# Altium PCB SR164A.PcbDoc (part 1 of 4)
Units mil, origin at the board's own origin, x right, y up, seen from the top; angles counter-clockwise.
Board outline 6100 x 4100 mil, 6 copper layers (Top Layer, Signal Layer 1, Signal Layer 2, Signal Layer 3, Signal Layer 4, Bottom Layer), stack 61.4 mil thick; 254 components, 116 nets, 656 pads, 2538 vias.
Unrouted connection lines stored in the file: 13.
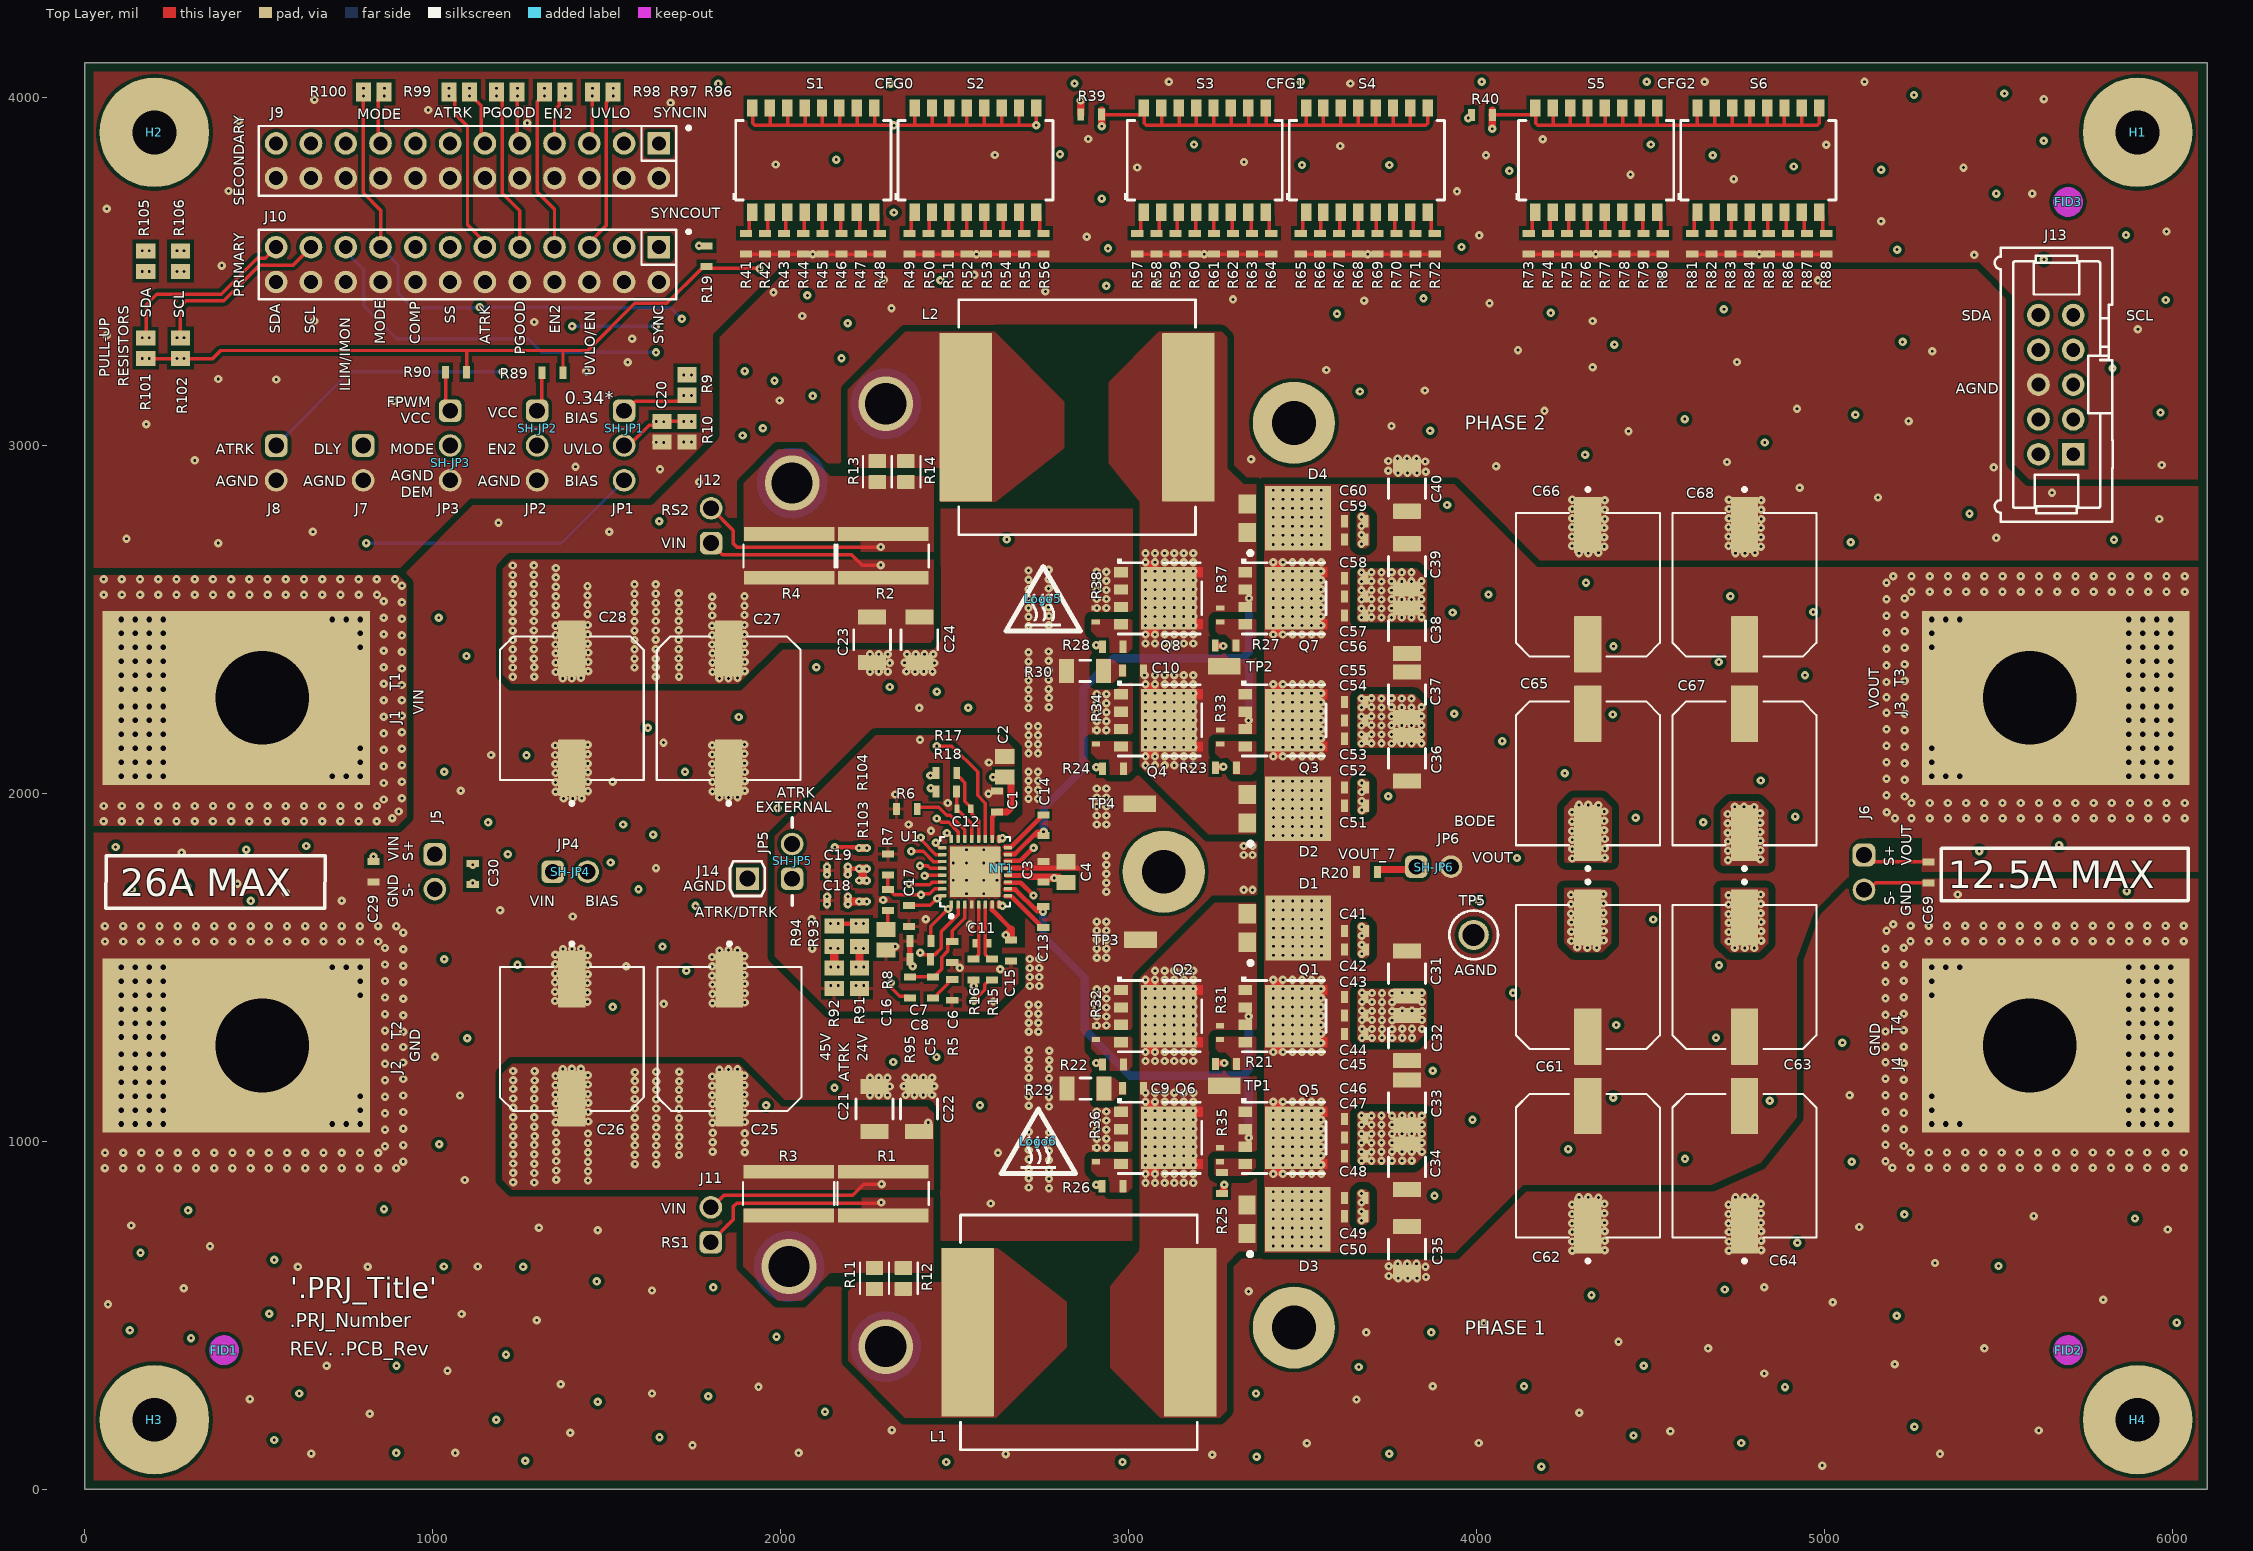
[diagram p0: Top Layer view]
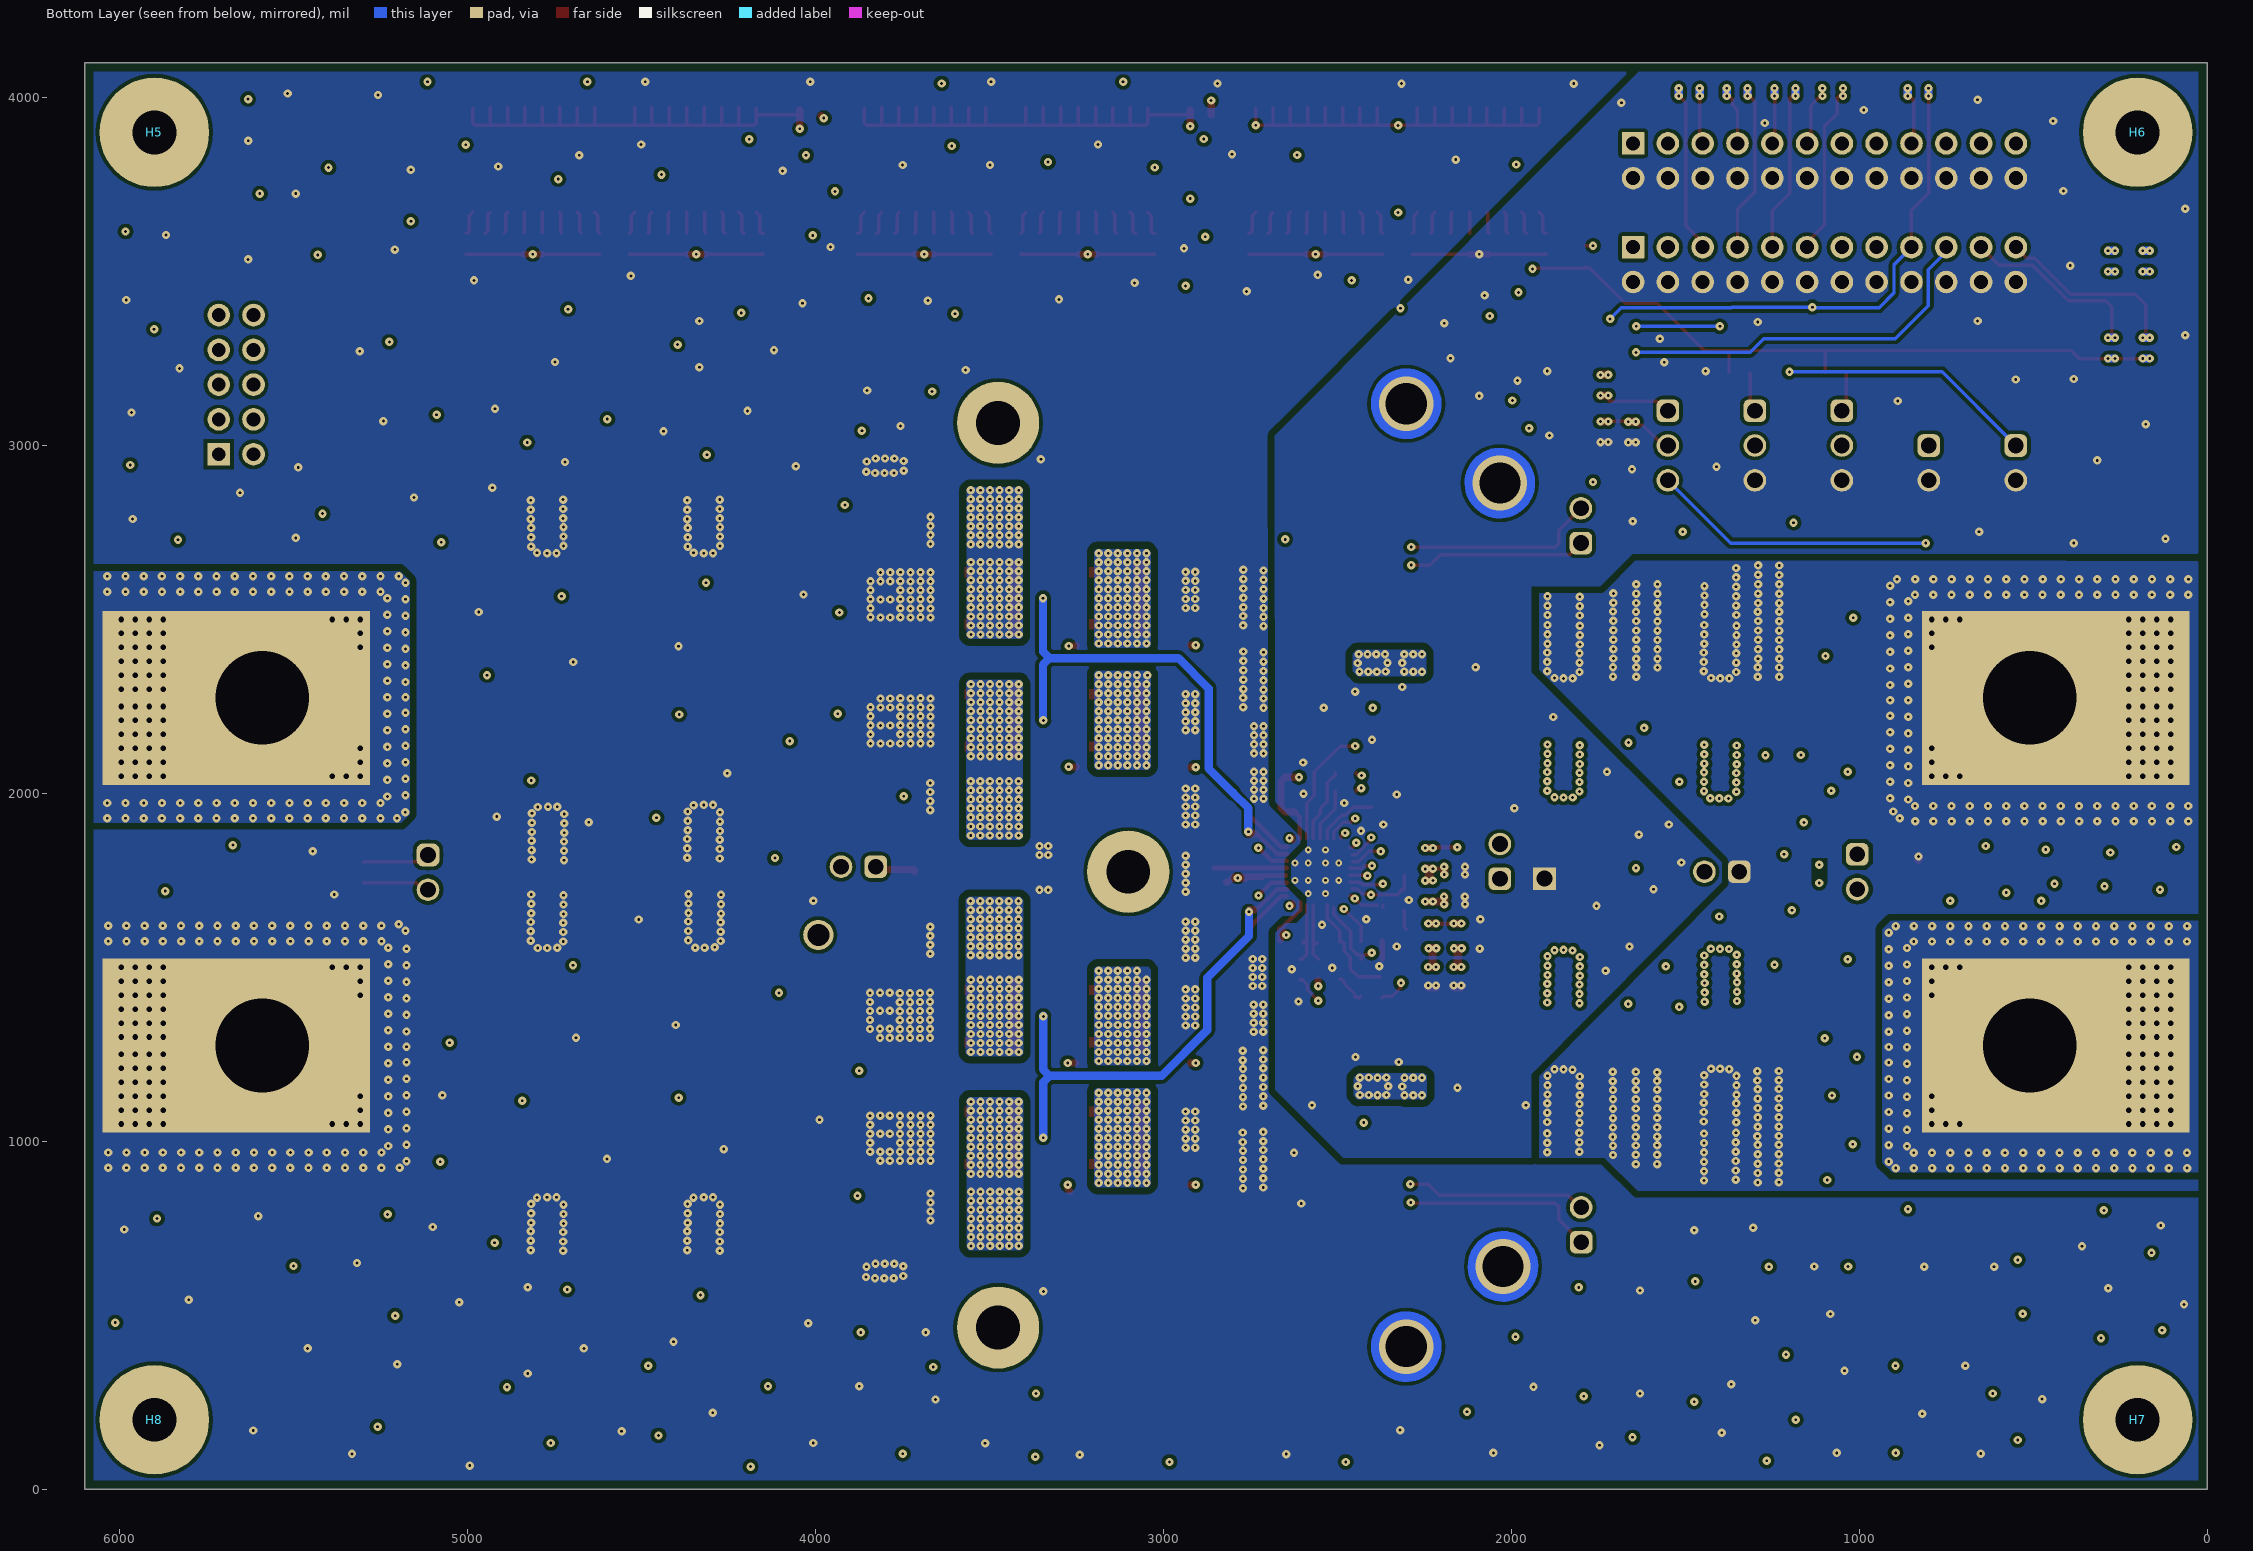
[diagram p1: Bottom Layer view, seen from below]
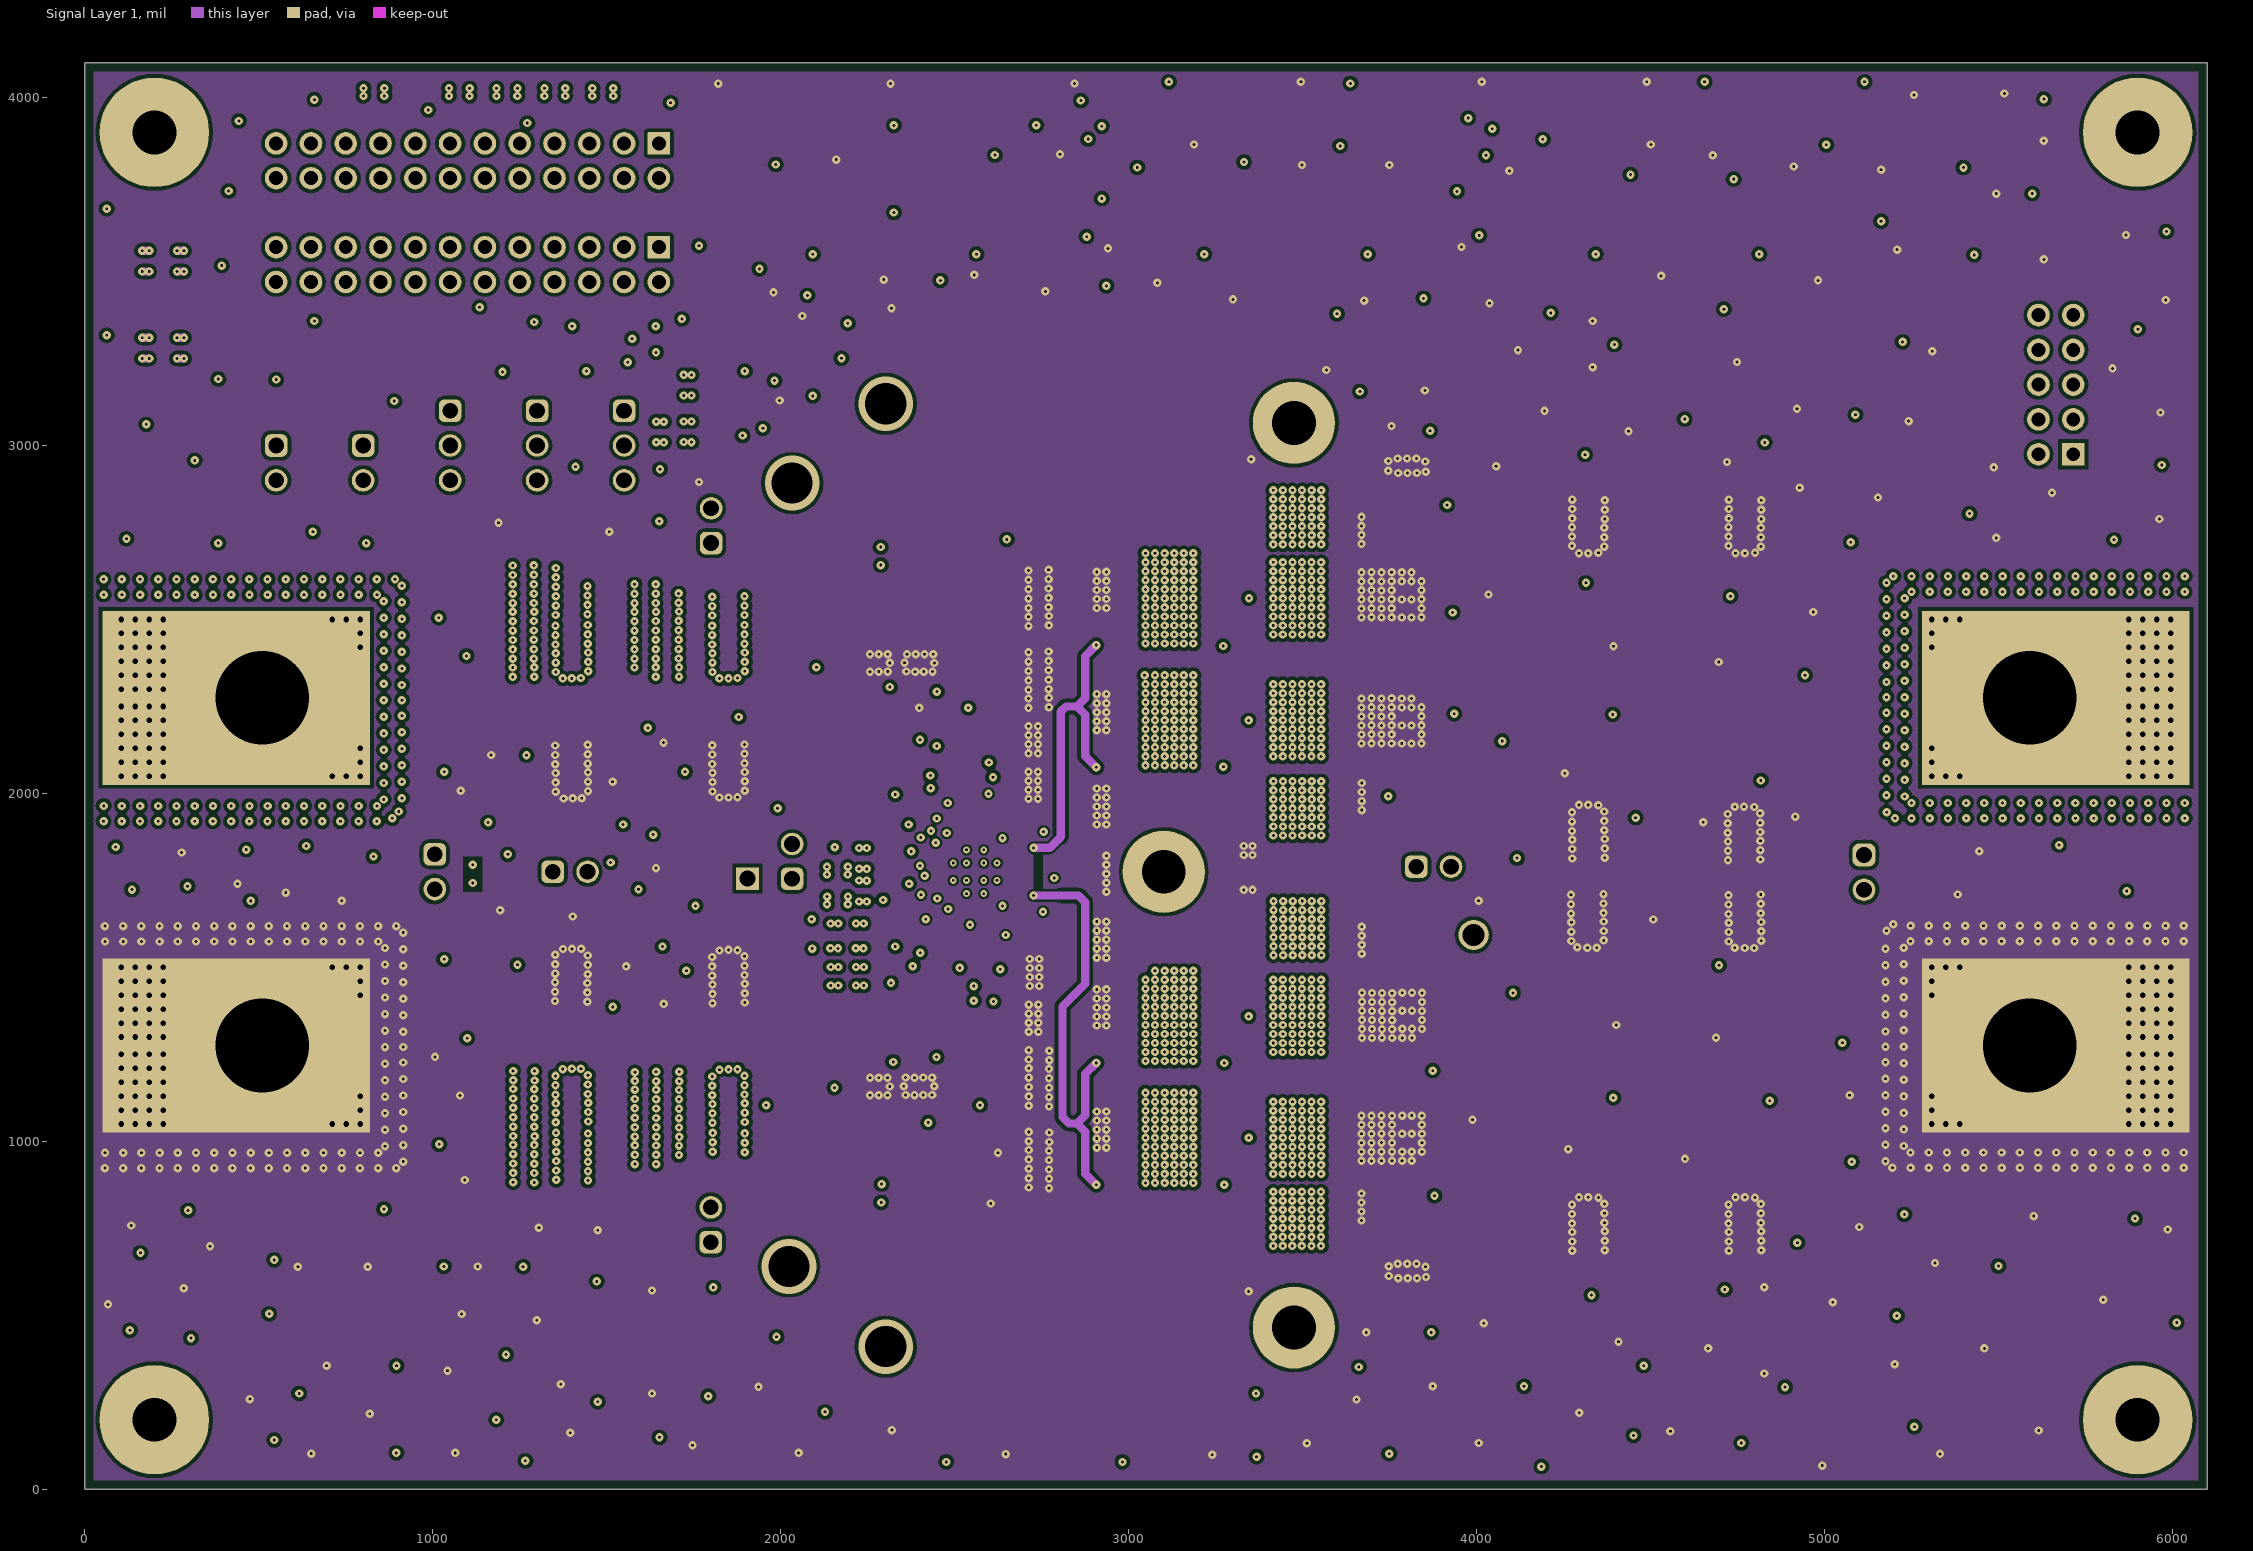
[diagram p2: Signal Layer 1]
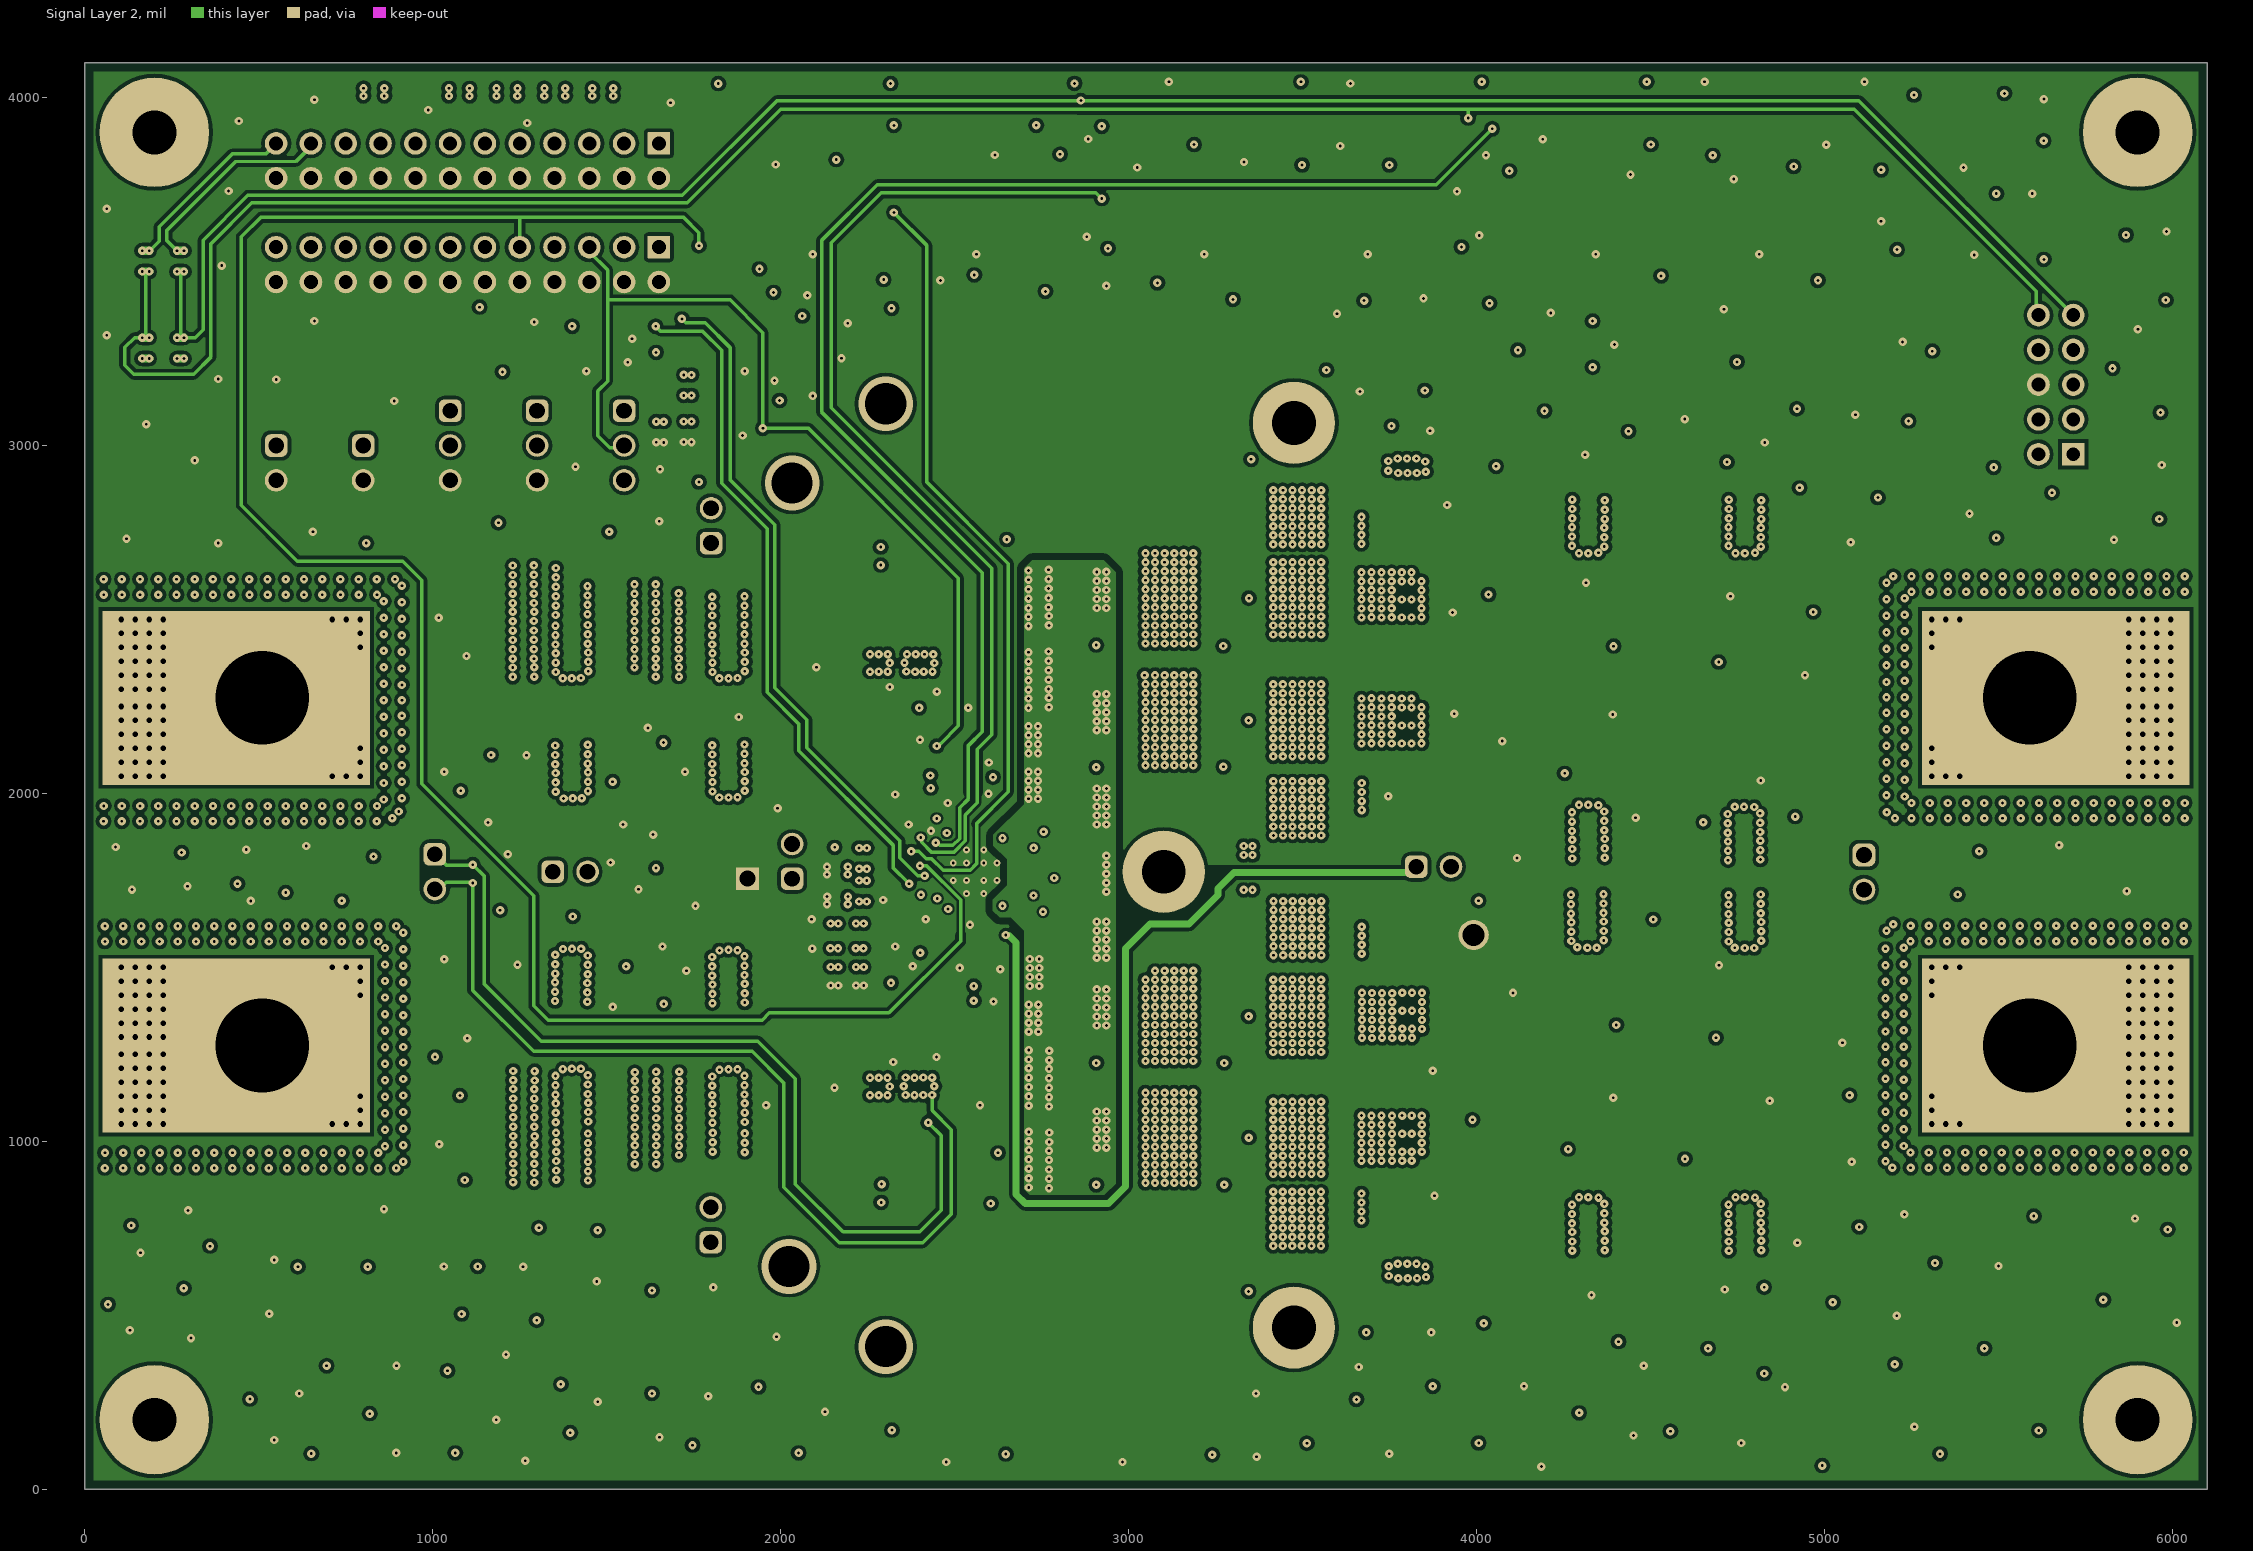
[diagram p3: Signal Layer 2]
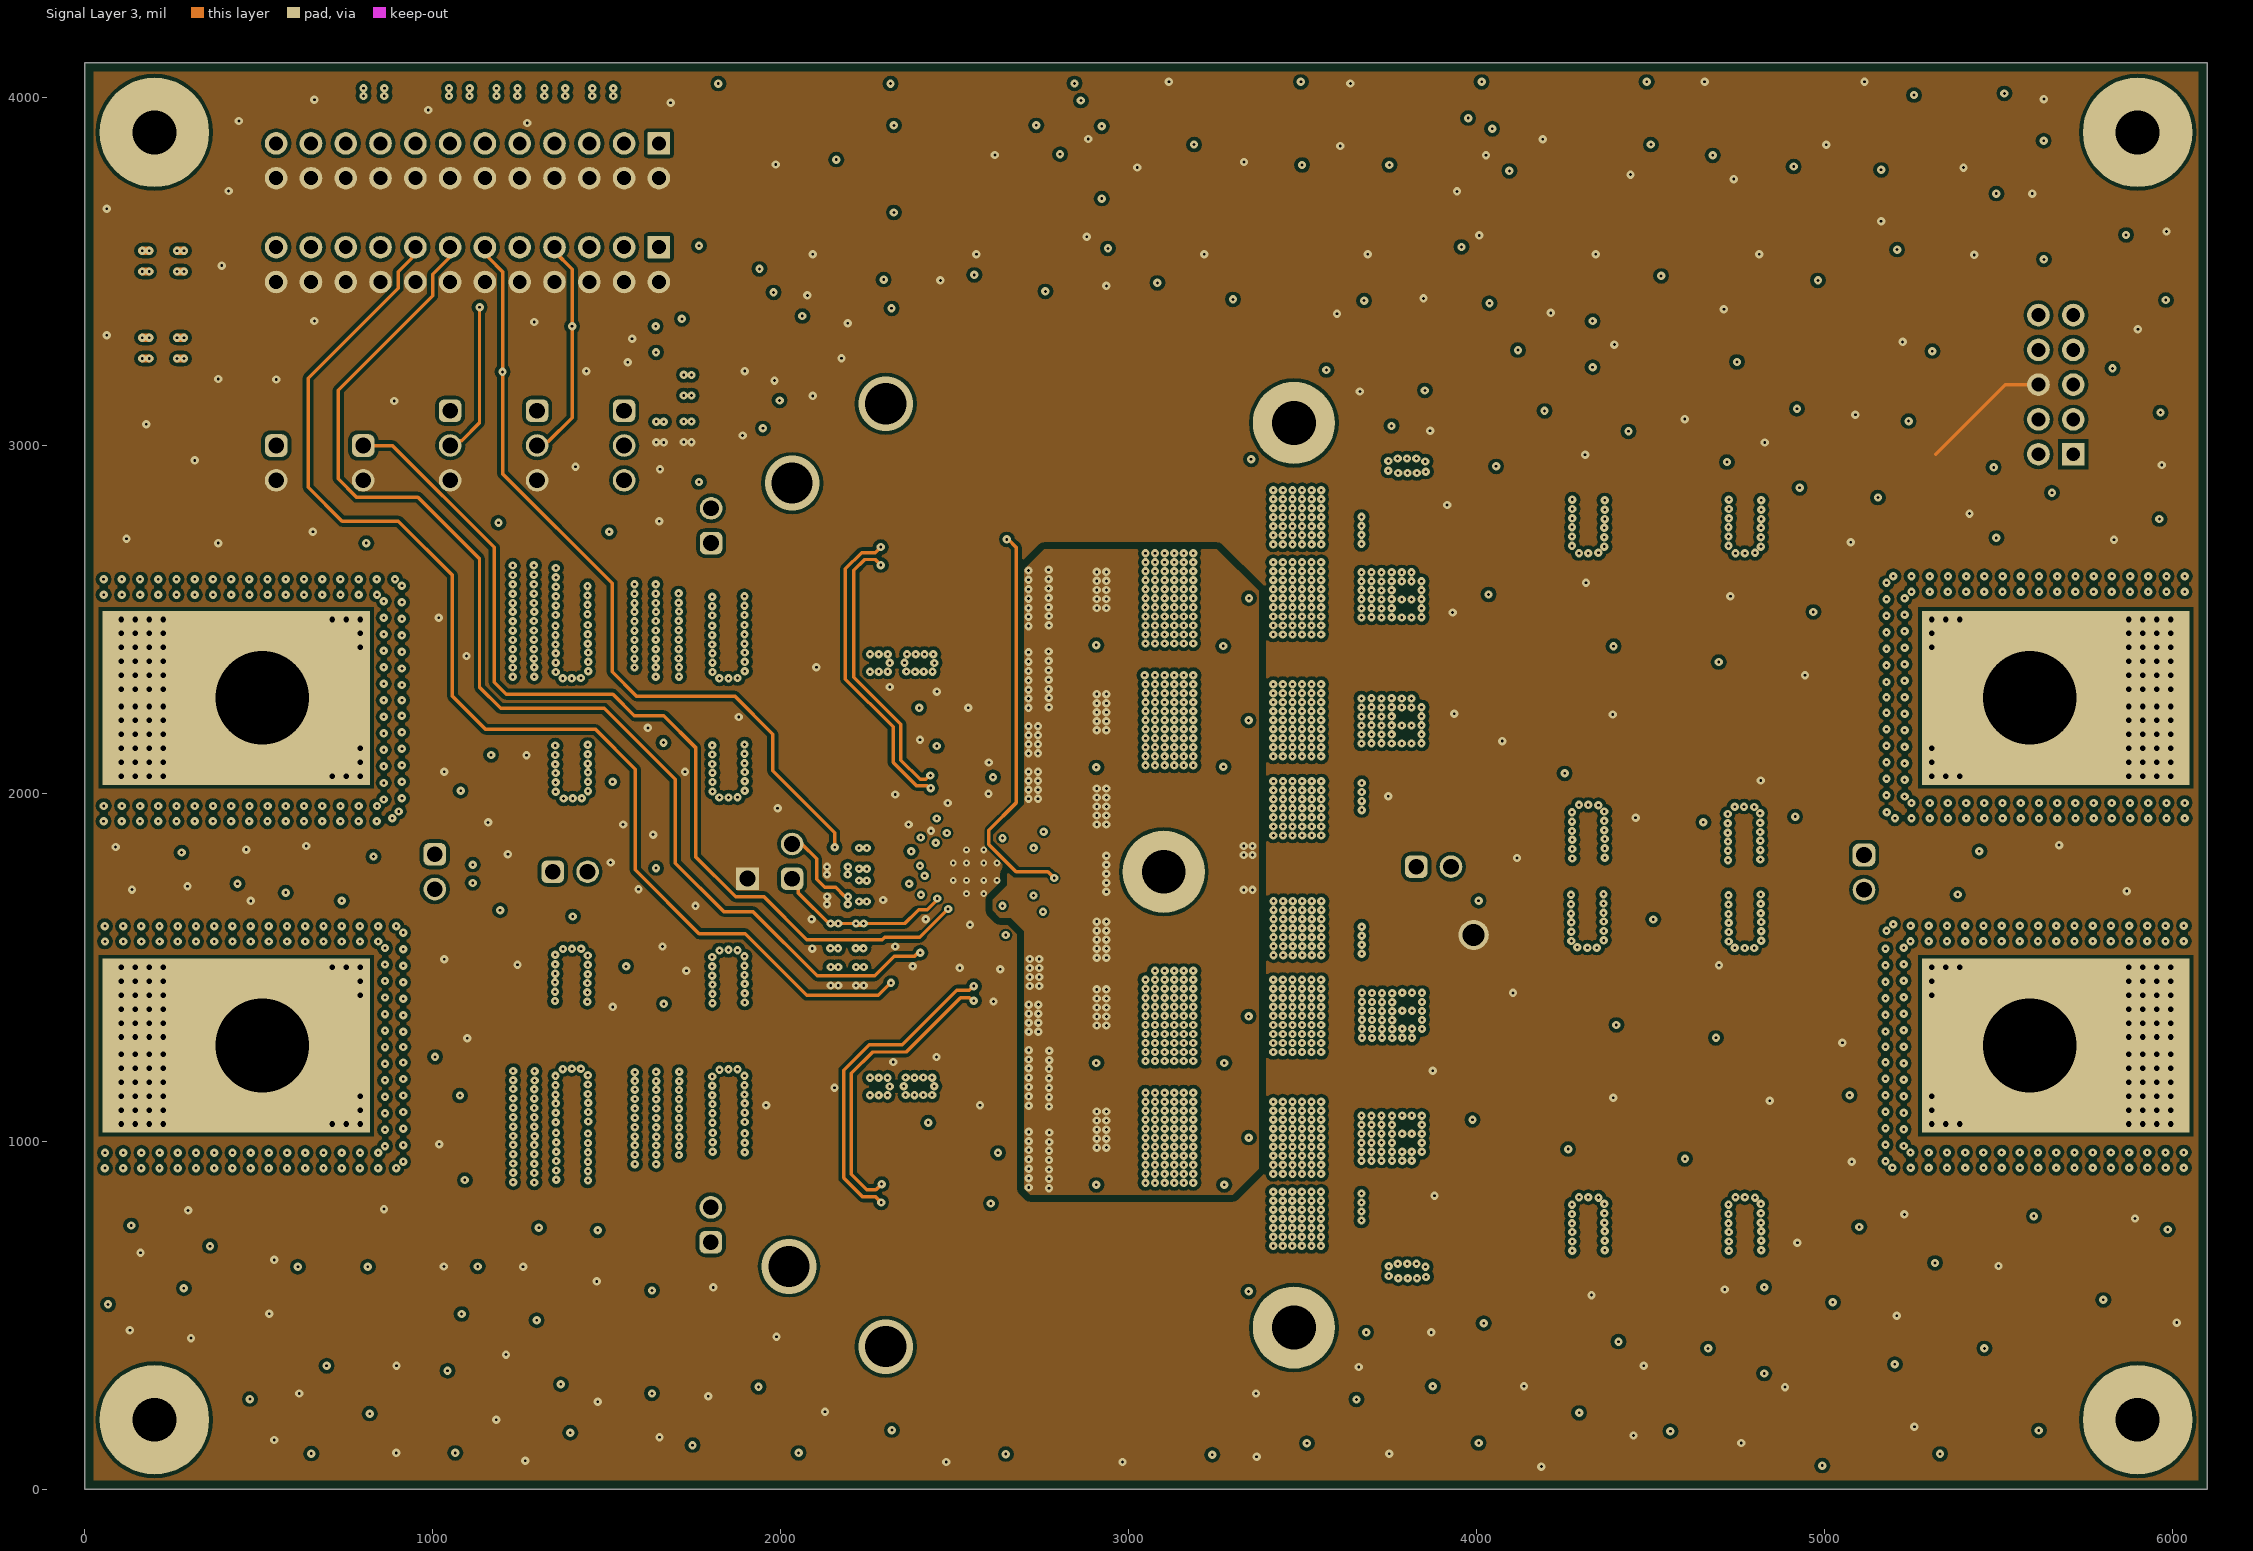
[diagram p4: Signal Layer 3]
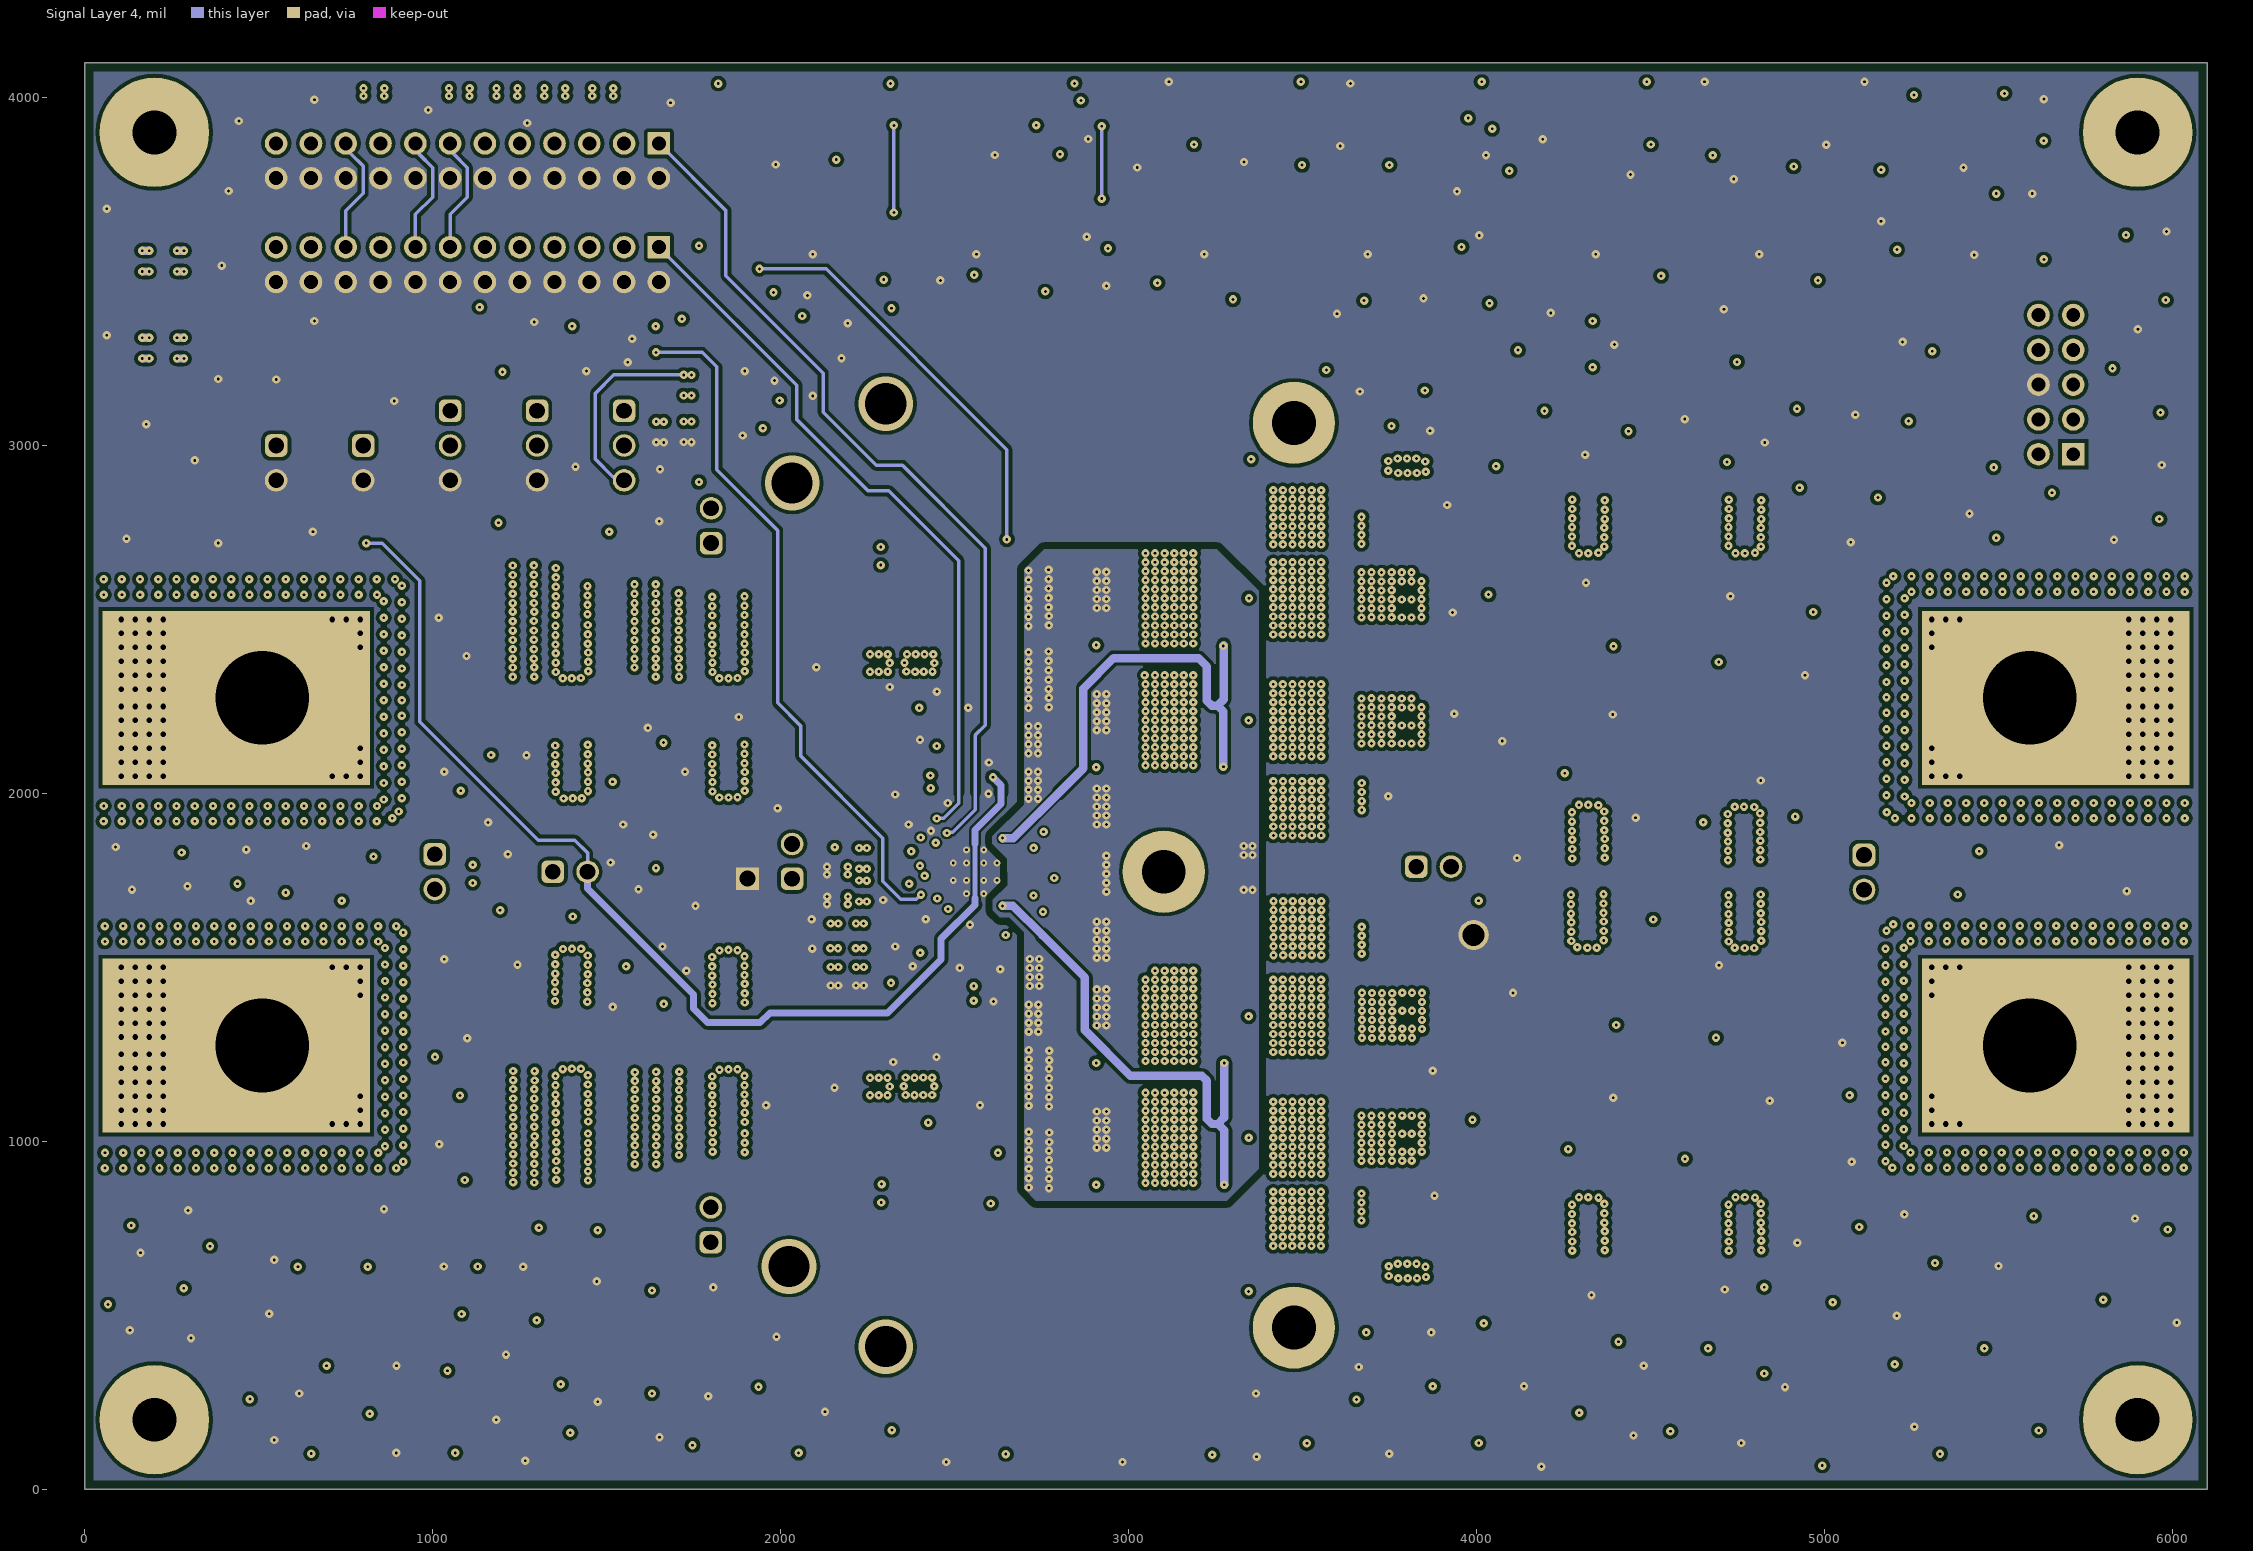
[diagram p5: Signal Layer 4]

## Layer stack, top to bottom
Top Solder: solder mask 0.5, Solder Resist, Dk 3.5
Top Layer: signal copper 2.8
Dielectric 1: prepreg 7, FR-4 High Tg, Dk 4.2
Signal Layer 1: signal copper 1.4
Dielectric 2: core 14, FR-4 High Tg, Dk 4.2
Signal Layer 2: signal copper 1.4
Dielectric 4: prepreg 8.2, FR-4 High Tg, Dk 4.2
Signal Layer 3: signal copper 1.4
Dielectric 5: core 14, FR-4 High Tg, Dk 4.2
Signal Layer 4: signal copper 1.4
Dielectric 3: prepreg 7, FR-4 High Tg, Dk 4.2
Bottom Layer: signal copper 2.8
Bottom Solder: solder mask 0.5, Solder Resist, Dk 3.5

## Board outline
0,0 6100,0 6100,4100 0,4100

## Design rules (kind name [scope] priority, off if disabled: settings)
AcuteAngle [All] p1: minimum=4.50000000000000E+0001 checktracksonly=FALSE
AssemblyTestPointUsage [All] p1: valid=2
BoardOutlineClearance BoardOutlineClearance_MountingHoles [OnCopper and InComponentClass('Mounting Holes')] p1: gap=39.37 ignorepadtopadclearanceinfootprint=FALSE
BoardOutlineClearance BoardOutlineClearance_Poly [OnCopper and IsPoly] p2: gap=25 ignorepadtopadclearanceinfootprint=FALSE
BoardOutlineClearance [OnCopper and Not InComponentClass('Logo') and not InComponentClass('FiducialMark') and not InRegion(1000,500,4000,800) and not InPoly] p3: gap=40 ignorepadtopadclearanceinfootprint=FALSE
Clearance Clearance_IC [WithinRoom('IC_Room')] p1: gap=6 ignorepadtopadclearanceinfootprint=TRUE
Clearance Clearance_Keepouts [((IsTrack Or IsArc) And Not InPoly) And IsFree and IsKeepOut vs ((IsTrack Or IsArc) And Not InPoly) And IsFree and IsKeepOut] p2: gap=0 ignorepadtopadclearanceinfootprint=FALSE
Clearance Clearance_Poly [InPolygon] p3: gap=10 ignorepadtopadclearanceinfootprint=TRUE except(20: Poly-Poly)
Clearance Clearance_FiducialMark [IsKeepOut and InComponentClass('FiducialMark') vs IsPad and InComponentClass('FiducialMark')] p4: gap=0 ignorepadtopadclearanceinfootprint=FALSE
Clearance [All] p5: gap=7.87 ignorepadtopadclearanceinfootprint=TRUE
ComponentClearance ComponentClearance_Banana [HasFootprint('Johnson_108-0740-001') vs HasFootprint('Panduit_CXS70-14-C')] p1: gap=-39.37 collisioncheckmode=3 verticalgap=0 showdistances=FALSE
ComponentClearance ComponentClearance_JP_Res [InComponent('JP6') or InComponent('JP7') or InComponent('R1') or InComponent('R2') or InComponent('R3') or InComponent('R4') or InComponent('R11') or InComponent('R13') or InComponent('J11') or InComponent('J12') or  InComponent('J27') or InComponent('J28')] p2: gap=0 collisioncheckmode=3 verticalgap=0 showdistances=FALSE
ComponentClearance ComponentClearance_NT [InComponent('U1') or InComponent('NT1')] p3: gap=-39.37 collisioncheckmode=3 verticalgap=0 showdistances=FALSE
ComponentClearance ComponentClearance_MountingHoles_FiducialMarks [InComponentClass('Mounting Holes') vs InComponentClass('FiducialMark')] p4: gap=50 collisioncheckmode=3 verticalgap=10 showdistances=FALSE
ComponentClearance ComponentClearance_Shunt [InComponentClass('Header') vs InComponentClass('Shunt') or InComponent('SH-JP1') or InComponent('SH-JP2') or InComponent('SH-JP3') or InComponent('SH-JP4') or InComponent('SH-JP5') or InComponent('SH-JP6') or  InComponent('SH-JP8')  or  InComponent('SH-JP9')] p5: gap=0 collisioncheckmode=3 verticalgap=0 showdistances=FALSE
ComponentClearance ComponentClearance_Logo [InComponentClass('Logo')] p6: gap=30 collisioncheckmode=3 verticalgap=10 showdistances=FALSE
ComponentClearance ComponentClearance_ScrewToNut [(HasFootprint('NY PMS 440 0025 PH')) vs (HasFootprint('Keystone_1902C'))] p7: gap=5 collisioncheckmode=3 verticalgap=10 showdistances=FALSE
ComponentClearance ComponentClearance_MountingHoles [InComponentClass('Mounting Holes')] p8: gap=100 collisioncheckmode=3 verticalgap=100000 showdistances=FALSE
ComponentClearance ComponentClearance_SmallPassives [HasFootprint('0201*') or HasFootprint('0402*') or HasFootprint('0508') or HasFootprint('0603*') or HasFootprint('0612') or HasFootprint('0805*') or HasFootprint('0815*') or HasFootprint('0830*') or HasFootprint('1206*') or HasFootprint('1210*') or HasFootprint('1808*') or HasFootprint('1812*') or HasFootprint('1825*') or HasFootprint('2010*') or HasFootprint('2220*') or HasFootprint('2225*') or HasFootprint('2512*') or HasFootprint('2728*') or HasFootprint('3518*') vs HasFootprint('0201*') or HasFootprint('0402*') or HasFootprint('0508') or HasFootprint('0603*') or HasFootprint('0612') or HasFootprint('0805*') or HasFootprint('0815*') or HasFootprint('0830*') or HasFootprint('1206*') or HasFootprint('1210*') or HasFootprint('1808*') or HasFootprint('1812*') or HasFootprint('1825*') or HasFootprint('2010*') or HasFootprint('2220*') or HasFootprint('2225*') or HasFootprint('2512*') or HasFootprint('2728*') or HasFootprint('3518*')] p9: gap=14.96 collisioncheckmode=3 verticalgap=10 showdistances=FALSE
ComponentClearance ComponentClearance_THtoSMT [IsThruComponent vs IsSMTComponent] p10: gap=30 collisioncheckmode=3 verticalgap=30 showdistances=FALSE
ComponentClearance ComponentClearance_THtoTH [IsThruComponent vs IsThruComponent] p11: gap=20 collisioncheckmode=3 verticalgap=30 showdistances=FALSE
ComponentClearance [All] p12: gap=15 collisioncheckmode=3 verticalgap=10 showdistances=FALSE
DiffPairsRouting [All] p1: maxlimit=100 minlimit=10 mostfreqgap=10 toplayer_minwidth=15 toplayer_maxwidth=15 toplayer_prefwidth=15 midlayer1_minwidth=15 midlayer1_maxwidth=15 midlayer1_prefwidth=15 midlayer2_minwidth=15 midlayer2_maxwidth=15 midlayer2_prefwidth=15 midlayer3_minwidth=15 midlayer3_maxwidth=15 midlayer3_prefwidth=15 midlayer4_minwidth=15 midlayer4_maxwidth=15 midlayer4_prefwidth=15 bottomlayer_minwidth=15 bottomlayer_maxwidth=15 bottomlayer_prefwidth=15 maxuncoupledlength=1000
FabricationTestPointUsage TestPointUsage [All] p1: valid=2 allowmultiple=FALSE
FabricationTestpoint Testpoint [All] p1: side=3 testpointundercomponent=TRUE minsize=40 maxsize=100 preferedsize=60 minholesize=0 maxholesize=40 preferedholesize=32 testpointgrid=1 allowsidetop=TRUE allowsidebottom=TRUE usegrid=TRUE gridtolerance=0.01
FanoutControl Fanout_LCC [IsLCC] p1: bgadir=Out bgaviamode=Centered fanoutstyle=Auto fanoutdirection=Alternating viagrid=1 // Fanout_LCC (Default Rule)
FanoutControl Fanout_BGA [IsBGA] p2: bgadir=Out bgaviamode=Centered fanoutstyle=Auto fanoutdirection=Alternating viagrid=1 // Fanout_BGA (Default Rule)
FanoutControl Fanout_Default [All] p4: bgadir=Out bgaviamode=Centered fanoutstyle=Auto fanoutdirection=Alternating viagrid=1 // Fanout_Default (Default Rule)
FanoutControl Fanout_Small [(CompPinCount < 5)] p5: bgadir=Out bgaviamode=Centered fanoutstyle=Auto fanoutdirection=OutThenIn viagrid=1 // Fanout_Small (Default Rule)
HoleSize [All] p1: absolutevalues=TRUE maxlimit=270 minlimit=7.87 maxpercent=80.000 minpercent=20.000
HoleToHoleClearance HoleToHoleClearance_Banana [HasFootprint('Johnson_108-0740-001') vs HasFootprint('Panduit_CXS70-14-C')] p1: gap=0 allowstackedmicrovias=TRUE
HoleToHoleClearance [All] p2: gap=10 allowstackedmicrovias=TRUE
MinimumAnnularRing MinimumAnnularRing_ThermalPadVias [IsVia and InAnyComponent] p1: minimumring=5.91
MinimumAnnularRing [All] p2: minimumring=7.87
MinimumSolderMaskSliver MinimumSolderMaskSliver_Logo [InComponentClass('Logo') vs InComponentClass('Logo')] p1: minsoldermaskwidth=0.7
MinimumSolderMaskSliver [All] p2: minsoldermaskwidth=3.94
PlaneConnect [All] p1: planeconnectstyle=Direct reliefexpansion=10 reliefentries=4 reliefconductorwidth=10 reliefairgap=10
PolygonConnect PolygonConnect_solder [InComponent('R5') or InComponent('R6') or InComponent('R7') or InComponent('R91') or InComponent('R92') or InComponent('C6') or InComponent('C7') or InComponent('C8') or InComponent('C15') or InComponent('C16') or InComponent('C17') or InComponent('C18') or InComponent('C19')] p1: connectstyle=Relief reliefconductorwidth=10 reliefentries=4 polygonreliefangle="90 Angle" airgapwidth=10
PolygonConnect [All] p2: connectstyle=Direct reliefconductorwidth=10 reliefentries=4 polygonreliefangle="90 Angle" airgapwidth=10
RoomDefinition IC_Room [InComponentClass('Top Side Components')] p1: confinementstyle=ConfineIn formatcopy=TRUE lockcomponents=FALSE outline 2392.15,2001.6 2805,2001.6 2805,1592.6 2392.15,1592.6
RoutingVias ThermalPadVias [IsVia and InAnyComponent] p1: holewidth=7.87 width=19.68 viastyle="Through Hole" minholewidth=7.87 minwidth=16 maxholewidth=16 maxwidth=32
RoutingVias [All] p2: holewidth=16 width=34 viastyle="Through Hole" minholewidth=7.87 minwidth=24 maxholewidth=270 maxwidth=270
SilkToBoardRegionClearance [Not ((IsComment or IsDesignator) And (Hide <> 'False')) and not InRegion(1000,500,4000,800)] p1:
SilkToSilkClearance SilkToSilkClearance_Pb-FreeLogo [(HasFootprint('Pb-Free_Overlay_Medium') OR HasFootprint('Pb-Free_Overlay_Small')) vs (HasFootprint('Pb-Free_Overlay_Medium') OR HasFootprint('Pb-Free_Overlay_Small'))] p1: silktosilkclearance=0
SilkToSilkClearance [All] p2: silktosilkclearance=3.94
SilkToSolderMaskClearance SilkToComponentPadClearance [(IsPad or IsFill or IsRegion) and InAnycomponent] p1: minsilkscreentomaskgap=5 clearancetoexposedcopper=TRUE
SilkToSolderMaskClearance "Silk to Solder Mask Opening" [All] p2: minsilkscreentomaskgap=3.94 clearancetoexposedcopper=FALSE
SolderMaskExpansion [All] p1: expansion=1.97 istentingtop=FALSE
SupplyNets "Schematic Supply Nets_1" [InNet('GND')] p1: voltage=0.000
SupplyNets "Schematic Supply Nets" [InNet('AGND')] p2: voltage=0.000
UnRoutedNet [All] p1: checkbadconnections=TRUE
Width [All] p1: maxlimit=100 minlimit=6 preferedwidth=10 checkconnectedcopper=TRUE
13 further rules are at their usual default settings.

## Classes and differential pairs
component class Shunt: SH-JP1 SH-JP2 SH-JP3 SH-JP4 SH-JP5 SH-JP6
component class Header: J5 J6 J7 J8 J9 J10 J11 J12 J14 JP1 JP2 JP3 JP4 JP5 JP6
component class SR164B: C1 C2 C3 C4 C5 C6 C7 C8 C9 C10 C11 C12 C13 C14 C15 C16 C17 C18 C19 C20 C21 C22 C23 C24 C25 C26 C27 C28 C29 C30 C31 C32 C33 C34 C35 C36 C37 C38 C39 C40 C41 C42 C43 C44 C45 C46 C47 C48 C49 C50 C51 C52 C53 C54 C55 C56 C57 C58 C59 C60 C61 C62 C63 C64 C65 C66 C67 C68 C69 D1 D2 D3 D4 J1 J2 J3 J4 J5 J6 J7 J8 J9 J10 J11 J12 J13 J14 JP1 JP2 JP3 JP4 JP5 JP6 L1 L2 NT1 Q1 Q2 Q3 Q4 Q5 Q6 Q7 Q8 R1 R2 R3 R4 R5 R6 R7 R8 R9 R10 R11 R12 R13 R14 R15 R16 R17 R18 R19 R20 R21 R22 R23 R24 R25 R26 R27 R28 R29 R30 R31 R32 R33 R34 R35 R36 R37 R38 R39 R40 R41 R42 R43 R44 R45 R46 R47 R48 R49 R50 R51 R52 R53 R54 R55 R56 R57 R58 R59 R60 R61 R62 R63 R64 R65 R66 R67 R68 R69 R70 R71 R72 R73 R74 R75 R76 R77 R78 R79 R80 R81 R82 R83 R84 R85 R86 R87 R88 R89 R90 R91 R92 R93 R94 R95 R96 R97 R98 R99 R100 R101 R102 R103 R104 R105 R106 S1 S2 S3 S4 S5 S6 SH-JP1 SH-JP2 SH-JP3 SH-JP4 SH-JP5 SH-JP6 T1 T2 T3 T4 TP1 TP2 TP3 TP4 TP5 U1
component class "Mounting Holes": H1 H2 H3 H4
component class SR164B_Hardware: FID1 FID2 FID3 H1 H2 H3 H4 H5 H6 H7 H8 Logo5 Logo6 ZZ2 ZZ3 ZZ4 ZZ5 ZZ6 ZZ7 ZZ8 ZZ9 ZZ10
component class FiducialMark: FID1 FID2 FID3
component class AssemblyNote: ZZ2 ZZ3 ZZ4 ZZ5 ZZ6 ZZ7 ZZ8 ZZ9 ZZ10

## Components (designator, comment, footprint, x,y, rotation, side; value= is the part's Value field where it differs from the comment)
C1 "GRM188R72A104KA35D" 0603S 2621.99,1977.06 r90 top value=0.1uF
C2 "GCM21BR71H105KA03K" 0805L 2644.25,2076.3 r270 top value=1uF
C3 "GRM188R72A104KA35D" 0603S 2755.75,1775 r90 top value=0.1uF
C4 "GCJ21BR71A106KE01L" 0805L 2819.75,1774.24 r90 top value=10uF
C5 "GCM188R72A153KA37D" 0603S 2437.93,1442.08 r270 top value=0.015uF
C6 "CC0603JRNPO9BN501" 0603S 2493.06,1544.14 r270 top value=500pF
C7 "C1608C0G1H100D080AA" 0603S 2401.68,1575.86 r180 top value=10pF
C8 "C0603C334K8PACTU" 0603S 2401.16,1523.34 r180 top value=0.33uF
C9 "C0603C681K5RACTU" 0603S 3012.67,1152.87 r180 top value=680pF
C10 "C0603C681K5RACTU" 0603S 3012.54,2353 r180 top value=680pF
C11 "04025A680FAT2A" 0402S 2578.41,1569.32 r180 top value=68pF
C12 "04025A680FAT2A" 0402S 2526.58,1956.52 r0 top value=68pF
C13 "GRM188R72A104KA35D" 0603S 2754.82,1644.96 r270 top value=0.1uF
C14 "GRM188R72A104KA35D" 0603S 2755.75,1908.61 r270 top value=0.1uF
C15 "GRM188R72A104KA35D" 0603S 2661.77,1548.98 r270 top value=0.1uF
C16 "C2012X7R1E335K125AB" 0805L 2302.35,1579.93 r270 top value=3.3uF
C17 "C1608C0G1H101J080AE" 0603S 2369.19,1648.24 r270 top value=100pF
C18 "C1608X7R1H473K080AA" 0603S 2163.28,1692.52 r180 top value=0.047uF
C19 "C1608X7R1H473K080AA" 0603S 2163.09,1778.19 r180 top value=0.047uF
C20 "CGA4J2X7R2A104K125AA" 0805L 1658.53,3039.67 r270 top value=0.1uF
C21 "GRM32EC72A106KE05L" FP-GRM32EC72A106KE05L_1210-MFG 2269.63,1093.22 r270 top
C22 "GRM32EC72A106KE05L" FP-GRM32EC72A106KE05L_1210-MFG 2397.73,1093.22 r270 top
C23 "GRM32EC72A106KE05L" FP-GRM32EC72A106KE05L_1210-MFG 2262.83,2441.92 r90 top
C24 "GRM32EC72A106KE05L" FP-GRM32EC72A106KE05L_1210-MFG 2398.67,2441.92 r90 top
C25 "EEHZU1H221P" FP-EEHZU1H221P_RADIAL_SMT-MFG 1852.77,1294.53 r270 top value=220µF
C26 "EEHZU1H221P" FP-EEHZU1H221P_RADIAL_SMT-MFG 1399.82,1294.53 r270 top value=220µF
C27 "EEHZU1H221P" FP-EEHZU1H221P_RADIAL_SMT-MFG 1850.6,2245 r90 top value=220µF
C28 "EEHZU1H221P" FP-EEHZU1H221P_RADIAL_SMT-MFG 1399.82,2245 r90 top value=220µF
C29 "GRM188R72A104KA35D" 0603S 830,1775 r270 top value=0.1uF
C30 "GRM188R72A104KA35D" 0603S 1114.78,1768.75 r270 top value=0.1uF
C31 "GRM32EC72A106KE05L" FP-GRM32EC72A106KE05L_1210-MFG 3800,1482.32 r90 top
C32 "GRM32EC72A106KE05L" FP-GRM32EC72A106KE05L_1210-MFG 3800,1296.89 r270 top
C33 "GRM32EC72A106KE05L" FP-GRM32EC72A106KE05L_1210-MFG 3800,1111.43 r90 top
C34 "GRM32EC72A106KE05L" FP-GRM32EC72A106KE05L_1210-MFG 3800,926.77 r270 top
C35 "GRM32EC72A106KE05L" FP-GRM32EC72A106KE05L_1210-MFG 3800.43,689.89 r90 top
C36 "GRM32EC72A106KE05L" FP-GRM32EC72A106KE05L_1210-MFG 3800,2100.83 r270 top
C37 "GRM32EC72A106KE05L" FP-GRM32EC72A106KE05L_1210-MFG 3800,2283.89 r90 top
C38 "GRM32EC72A106KE05L" FP-GRM32EC72A106KE05L_1210-MFG 3800,2467.5 r270 top
C39 "GRM32EC72A106KE05L" FP-GRM32EC72A106KE05L_1210-MFG 3800,2652.72 r90 top
C40 "GRM32EC72A106KE05L" FP-GRM32EC72A106KE05L_1210-MFG 3800,2876.12 r270 top
C41 "GRM188R72A104KA35D" 0603S 3650.61,1604.57 r0 top value=0.1uF
C42 "GRM188R72A104KA35D" 0603S 3650.61,1551.86 r0 top value=0.1uF
C43 "GRM188R72A104KA35D" 0603S 3650,1414.57 r0 top value=0.1uF
C44 "GRM188R72A104KA35D" 0603S 3650,1361.5 r0 top value=0.1uF
C45 "GRM188R72A104KA35D" 0603S 3650,1308.75 r0 top value=0.1uF
C46 "GRM188R72A104KA35D" 0603S 3650,1064.53 r0 top value=0.1uF
C47 "GRM188R72A104KA35D" 0603S 3650,1010.83 r0 top value=0.1uF
C48 "GRM188R72A104KA35D" 0603S 3650,957.19 r0 top value=0.1uF
C49 "GRM188R72A104KA35D" 0603S 3650,837.72 r0 top value=0.1uF
C50 "GRM188R72A104KA35D" 0603S 3650,785.03 r0 top value=0.1uF
C51 "GRM188R72A104KA35D" 0603S 3650.61,1964.69 r0 top value=0.1uF
C52 "GRM188R72A104KA35D" 0603S 3650.61,2017.38 r0 top value=0.1uF
C53 "GRM188R72A104KA35D" 0603S 3650,2157.16 r0 top value=0.1uF
C54 "GRM188R72A104KA35D" 0603S 3650,2209.73 r0 top value=0.1uF
C55 "GRM188R72A104KA35D" 0603S 3650,2262.92 r0 top value=0.1uF
C56 "GRM188R72A104KA35D" 0603S 3650,2511.9 r0 top value=0.1uF
C57 "GRM188R72A104KA35D" 0603S 3650,2566.06 r0 top value=0.1uF
C58 "GRM188R72A104KA35D" 0603S 3650,2618.58 r0 top value=0.1uF
C59 "GRM188R72A104KA35D" 0603S 3650,2729.72 r0 top value=0.1uF
C60 "GRM188R72A104KA35D" 0603S 3650,2782.43 r0 top value=0.1uF
C61 "EEHZU1J151P" FP-EEHZU1J151P_RADIAL_SMT-MFG 4320,1472.23 r270 top value=150µF
C62 "EEHZU1J151P" FP-EEHZU1J151P_RADIAL_SMT-MFG 4320.04,930 r90 top value=150µF
C63 "EEHZU1J151P" FP-EEHZU1J151P_RADIAL_SMT-MFG 4770,1472.23 r270 top value=150µF
C64 "EEHZU1J151P" FP-EEHZU1J151P_RADIAL_SMT-MFG 4770,930 r90 top value=150µF
C65 "EEHZU1J151P" FP-EEHZU1J151P_RADIAL_SMT-MFG 4320,2057.77 r90 top value=150µF
C66 "EEHZU1J151P" FP-EEHZU1J151P_RADIAL_SMT-MFG 4320,2600 r270 top value=150µF
C67 "EEHZU1J151P" FP-EEHZU1J151P_RADIAL_SMT-MFG 4770,2057.77 r90 top value=150µF
C68 "EEHZU1J151P" FP-EEHZU1J151P_RADIAL_SMT-MFG 4770,2600 r270 top value=150µF
C69 "GRM188R72A104KA35D" 0603S 5299.21,1772.85 r270 top value=0.1uF
D1 "V12P10-M3/86A" TO-277A 3413.42,1613.36 r90 top value=100V
D2 "V12P10-M3/86A" TO-277A 3412.9,1956.07 r90 top value=100V
D3 "V12P10-M3/86A" TO-277A 3412.29,776.41 r90 top value=100V
D4 "V12P10-M3/86A" TO-277A 3412.81,2791.22 r90 top value=100V
FID1 "Fiducial" Fiducial10-20 400,400 r0 top
FID2 "Fiducial" Fiducial10-20 5700,400 r0 top
FID3 "Fiducial" Fiducial10-20 5700,3700 r0 top
H1 "NY PMS 440 0025 PH" "NY PMS 440 0025 PH" 5900,3900 r0 top
H2 "NY PMS 440 0025 PH" "NY PMS 440 0025 PH" 200,3900 r0 top
H3 "NY PMS 440 0025 PH" "NY PMS 440 0025 PH" 200,200 r0 top
H4 "NY PMS 440 0025 PH" "NY PMS 440 0025 PH" 5900,200 r0 top
H5 "1902C" Keystone_1902C 5900,3900 r180 bottom
H6 "1902C" Keystone_1902C 200,3900 r180 bottom
H7 "1902C" Keystone_1902C 200,200 r180 bottom
H8 "1902C" Keystone_1902C 5900,200 r180 bottom
J1 "108-0740-001" Johnson_108-0740-001 510,2275 r0 top
J2 "108-0740-001" Johnson_108-0740-001 510,1275 r0 top
J3 "108-0740-001" Johnson_108-0740-001 5590,2275 r0 top
J4 "108-0740-001" Johnson_108-0740-001 5590,1275 r0 top
J5 "61300211121" WURTH_61300211121 1005.98,1775 r270 top
J6 "61300211121" WURTH_61300211121 5113.57,1773.15 r270 top
J7 "61300211121" WURTH_61300211121 800,2950 r270 top
J8 "61300211121" WURTH_61300211121 550,2950 r270 top
J9 "TSW-112-07-G-D" TSW-112-07-G-D 1100,3818.31 r180 top
J10 "TSW-112-07-G-D" TSW-112-07-G-D 1100,3520 r180 top
J11 "61300211121" WURTH_61300211121 1799.29,760.42 r90 top
J12 "61300211121" WURTH_61300211121 1800,2769.54 r90 top
J13 "Header_5x2" CONN_2510-6002 5665,3175 r90 top
J14 "61300111121" WURTH_61300111121 1904.58,1755.42 r0 top
JP1 "61300311121" WURTH_61300311121 1550,3000 r270 top
JP2 "61300311121" WURTH_61300311121 1300,3000 r270 top
JP3 "61300311121" WURTH_61300311121 1050,3000 r270 top
JP4 "61300211121" WURTH_61300211121 1395,1775 r0 top
JP5 "61300211121" WURTH_61300211121 2032.92,1804.76 r90 top
JP6 "61300211121" WURTH_61300211121 3876.55,1789.64 r0 top
L1 "IHLP6767GZER3R3M5A" IHLP-6767GZ 2857.07,451.15 r180 top value=3.3uH
L2 "IHLP6767GZER3R3M5A" IHLP-6767GZ 2851.96,3081.5 r0 top value=3.3uH
Logo5 "CAUTION HOT SURFACE" IEC_HotSurface_Small 2754.82,2560 r0 top
Logo6 "CAUTION HOT SURFACE" IEC_HotSurface_Small 2740.72,1000.36 r0 top
NT1 "Net-Tie" Net-Tie_10milWide_30milLong 2635.51,1784.93 r0 top net-tie
Q1 "NTM" SO-8FL 3445,1360 r0 top value=60V
Q2 "NTM" SO-8FL 3088,1360 r0 top value=60V
Q3 "NTM" SO-8FL 3445,2210 r0 top value=60V
Q4 "NTM" SO-8FL 3088,2210 r0 top value=60V
Q5 "NTM" SO-8FL 3445,1010 r0 top value=60V
Q6 "NTM" SO-8FL 3088,1010 r0 top value=60V
Q7 "NTM" SO-8FL 3445,2561 r0 top value=60V
Q8 "NTM" SO-8FL 3088,2561 r0 top value=60V
R1 "PML100HZPJV1L5" 2512_WIDE 2295,850 r90 top value=0.0015
R2 "PML100HZPJV1L5" 2512_WIDE 2294.96,2683 r90 top value=0.0015
R3 "PML100HZPJV1L5" 2512_WIDE 2023.43,850 r90 top value=0.0015
R4 "PML100HZPJV1L5" 2512_WIDE 2024.83,2683 r90 top value=0.0015
R5 "CRCW060320K0FKEA" 0603S 2493.11,1435.72 r90 top value=20.0k
R6 "RT0603BRD0778K7L" 0603S 2362.58,1955.35 r0 top value=78.7k
R7 "RT0603BRD0747K5L" 0603S 2308.21,1795.47 r270 top value=47.5k
R8 "CRCW06036K04FKEA" 0603S 2308.21,1693.87 r90 top value=6.04k
R9 "CRCW080575K0FKEA" 0805L 1730.98,3173.92 r270 top value=75.0k
R10 "CRCW080539K0JNEA" 0805L 1730.98,3040.08 r270 top value=39k
R11 "WSL080500000ZEA9" FP-WSL080500000ZEA9_0805-MFG 2269.63,606.2 r90 top value=0
R12 "WSL080500000ZEA9" FP-WSL080500000ZEA9_0805-MFG 2352.72,606.2 r90 top value=0
R13 "WSL080500000ZEA9" FP-WSL080500000ZEA9_0805-MFG 2278,2925.06 r90 top value=0
R14 "WSL080500000ZEA9" FP-WSL080500000ZEA9_0805-MFG 2360,2925.06 r90 top value=0
R15 "RMCF0603ZT0R00" 0603S 2607.6,1494.14 r270 top value=0
R16 "RMCF0603ZT0R00" 0603S 2554.63,1494.14 r270 top value=0
R17 "RMCF0603ZT0R00" 0603S 2476.08,2059.06 r180 top value=0
R18 "RMCF0603ZT0R00" 0603S 2475.92,2005.78 r180 top value=0
R19 "CRCW0603100KFKEA" 0603S 1786.95,3543.92 r90 top value=100k
R20 "CRCW060310R0FKEA" 0603S 3685.08,1774.24 r0 top value=10.0
R21 "ERJ-3RQF2R2V" 0603S 3280.39,1222.48 r180 top value=2.20
R22 "CRCW060310R0FKEA" 0603S 2955.22,1220.95 r0 top value=10.0
R23 "ERJ-3RQF2R2V" 0603S 3279.47,2073.93 r0 top value=2.20
R24 "CRCW060310R0FKEA" 0603S 2955.04,2070.84 r180 top value=10.0
R25 "ERJ-3RQF2R2V" 0603S 3268.23,880.71 r270 top value=2.20
R26 "CRCW060310R0FKEA" 0603S 2953.55,870.94 r0 top value=10.0
R27 "ERJ-3RQF2R2V" 0603S 3279.03,2425.38 r0 top value=2.20
R28 "CRCW060310R0FKEA" 0603S 2954.48,2421.85 r180 top value=10.0
R29 "CRCW12063R24FKEA" 1206L 2876.13,1151.36 r0 top value=3.24
R30 "CRCW12063R24FKEA" 1206L 2875,2352 r0 top value=3.24
R31 "CRCW0402100KFKED" 0402S 3262.73,1312.62 r270 top value=100k
R32 "CRCW0402100KFKED" 0402S 2906.31,1312.62 r270 top value=100k
R33 "CRCW0402100KFKED" 0402S 3263.4,2162.09 r270 top value=100k
R34 "CRCW0402100KFKED" 0402S 2906.31,2162.09 r270 top value=100k
R35 "CRCW0402100KFKED" 0402S 3262.73,961.61 r270 top value=100k
R36 "CRCW0402100KFKED" 0402S 2906.31,961.61 r270 top value=100k
R37 "CRCW0402100KFKED" 0402S 3263.4,2512.94 r270 top value=100k
R38 "CRCW0402100KFKED" 0402S 2905.41,2512.94 r270 top value=100k
R39 "RMCF0603ZT0R00" 0603S 2892.44,3951.1 r0 top value=0
R40 "RMCF0603ZT0R00" 0603S 4015.28,3950.31 r0 top value=0
R41 "RMCF0603ZT0R00" 0603S 1900,3580 r270 top value=0
R42 "CRCW0603511RFKEA" 0603S 1955,3580 r90 top value=511
R43 "CRCW06031K30FKEA" 0603S 2010,3580 r270 top value=1.30k
R44 "CRCW06031K87FKEA" 0603S 2065,3580 r90 top value=1.87k
R45 "CRCW06032K74FKEA" 0603S 2120,3580 r270 top value=2.74k
R46 "CRCW06033K83FKEA" 0603S 2175,3580 r90 top value=3.83k
R47 "CRCW06035K11FKEA" 0603S 2230,3580 r90 top value=5.11k
R48 "CRCW06036K49FKEA" 0603S 2285,3580 r90 top value=6.49k
R49 "CRCW06038K25FKEA" 0603S 2370,3580 r90 top value=8.25k
R50 "CRCW060310K5FKEA" 0603S 2425,3580 r90 top value=10.5k
R51 "CRCW060313K3FKEA" 0603S 2480,3580 r90 top value=13.3k
R52 "CRCW060316K2FKEA" 0603S 2535,3580 r270 top value=16.2k
R53 "CRCW060320K5FKEA" 0603S 2590,3580 r90 top value=20.5k
R54 "CRCW060324K9FKEA" 0603S 2645,3580 r90 top value=24.9k
R55 "CRCW060330K1FKEA" 0603S 2700,3580 r90 top value=30.1k
R56 "CRCW060336K5FKEA" 0603S 2755,3580 r270 top value=36.5k
R57 "RMCF0603ZT0R00" 0603S 3025,3580 r270 top value=0
R58 "CRCW0603511RFKEA" 0603S 3080,3580 r90 top value=511
R59 "CRCW06031K30FKEA" 0603S 3135,3580 r270 top value=1.30k
R60 "CRCW06031K87FKEA" 0603S 3190,3580 r90 top value=1.87k
R61 "CRCW06032K74FKEA" 0603S 3245,3580 r270 top value=2.74k
R62 "CRCW06033K83FKEA" 0603S 3300,3580 r90 top value=3.83k
R63 "CRCW06035K11FKEA" 0603S 3355,3580 r90 top value=5.11k
R64 "CRCW06036K49FKEA" 0603S 3410,3580 r90 top value=6.49k
R65 "CRCW06038K25FKEA" 0603S 3495,3580 r90 top value=8.25k
R66 "CRCW060310K5FKEA" 0603S 3550,3580 r90 top value=10.5k
R67 "CRCW060313K3FKEA" 0603S 3605,3580 r90 top value=13.3k
R68 "CRCW060316K2FKEA" 0603S 3660,3580 r270 top value=16.2k
R69 "CRCW060320K5FKEA" 0603S 3715,3580 r90 top value=20.5k
R70 "CRCW060324K9FKEA" 0603S 3770,3580 r90 top value=24.9k
R71 "CRCW060330K1FKEA" 0603S 3825,3580 r90 top value=30.1k
R72 "CRCW060336K5FKEA" 0603S 3880,3580 r270 top value=36.5k
R73 "RMCF0603ZT0R00" 0603S 4150,3580 r270 top value=0
R74 "CRCW0603511RFKEA" 0603S 4205,3580 r90 top value=511
R75 "CRCW06031K30FKEA" 0603S 4260,3580 r270 top value=1.30k
R76 "CRCW06031K87FKEA" 0603S 4315,3580 r90 top value=1.87k
R77 "CRCW06032K74FKEA" 0603S 4370,3580 r270 top value=2.74k
R78 "CRCW06033K83FKEA" 0603S 4425,3580 r90 top value=3.83k
R79 "CRCW06035K11FKEA" 0603S 4480,3580 r90 top value=5.11k
R80 "CRCW06036K49FKEA" 0603S 4535,3580 r90 top value=6.49k
R81 "CRCW06038K25FKEA" 0603S 4620,3580 r90 top value=8.25k
R82 "CRCW060310K5FKEA" 0603S 4675,3580 r90 top value=10.5k
R83 "CRCW060313K3FKEA" 0603S 4730,3580 r90 top value=13.3k
R84 "CRCW060316K2FKEA" 0603S 4785,3580 r270 top value=16.2k
R85 "CRCW060320K5FKEA" 0603S 4840,3580 r90 top value=20.5k
R86 "CRCW060324K9FKEA" 0603S 4895,3580 r90 top value=24.9k
R87 "CRCW060330K1FKEA" 0603S 4950,3580 r90 top value=30.1k
R88 "CRCW060336K5FKEA" 0603S 5005,3580 r270 top value=36.5k
R89 "CRCW06034K99FKEA" 0603S 1344.41,3209.02 r0 top value=4.99k
R90 "CRCW06034K99FKEA" 0603S 1067.3,3210.84 r0 top value=4.99k
R91 "CRCW08050000Z0EA" 0805L 2226.85,1469.17 r90 top value=0
R92 "CRCW08050000Z0EA" 0805L 2153.97,1469.17 r90 top value=0
R93 "CRCW080540K2FKEA" 0805L 2226.85,1589.21 r90 top value=40.2k
R94 "CRCW080575K0FKEA" 0805L 2153.97,1589.21 r90 top value=75.0k
R95 "ERJ-3GEY0R00V" 0603S 2371.77,1442.4 r90 top value=0
R96 "CRCW08050000Z0EA" 0805L 1488.43,4015.75 r180 top value=0
R97 "CRCW08050000Z0EA" 0805L 1350.75,4015.75 r0 top value=0
R98 "CRCW08050000Z0EA" 0805L 1213.06,4015.75 r0 top value=0
R99 "CRCW08050000Z0EA" 0805L 1076.4,4015.75 r0 top value=0
R100 "CRCW08050000Z0EA" 0805L 830.71,4015.75 r0 top value=0
R101 "CRCW080510K0FKEA" 0805L 175,3280 r270 top locked value=10.0k
R102 "CRCW080510K0FKEA" 0805L 275,3280 r270 top locked value=10.0k
R103 "CRCW06034K99FKEA" 0603S 2236.4,1719.66 r90 top value=4.99k
R104 "CRCW06034K99FKEA" 0603S 2236.35,1813.43 r90 top value=4.99k
R105 "CRCW08050000Z0EA" 0805L 175,3530 r90 top locked value=0
R106 "CRCW08050000Z0EA" 0805L 275,3530 r90 top locked value=0
S1 "218-8LPST" SW_218-8LP 2093.9,3820 r90 top
S2 "218-8LPST" SW_218-8LP 2560,3820 r90 top
S3 "218-8LPST" SW_218-8LP 3218.9,3820 r90 top
S4 "218-8LPST" SW_218-8LP 3685,3820 r90 top
S5 "218-8LPST" SW_218-8LP 4343.9,3820 r90 top
S6 "218-8LPST" SW_218-8LP 4810,3820 r90 top
SH-JP1 "SPC02SYAN" SPC02SYAN 1550,3050 r90 top value=1x2
SH-JP2 "SPC02SYAN" SPC02SYAN 1300,3050 r90 top value=1x2
SH-JP3 "SPC02SYAN" SPC02SYAN 1050,2950 r90 top value=1x2
SH-JP4 "SPC02SYAN" SPC02SYAN 1395,1775 r0 top value=1x2
SH-JP5 "SPC02SYAN" SPC02SYAN 2032.61,1806.2 r90 top value=1x2
SH-JP6 "SPC02SYAN" SPC02SYAN 3876.78,1787.91 r180 top value=1x2
T1 "CXS70-14-C" Panduit_CXS70-14-C 510,2275 r0 top
T2 "CXS70-14-C" Panduit_CXS70-14-C 510,1275 r0 top
T3 "CXS70-14-C" Panduit_CXS70-14-C 5590,2275 r180 top
T4 "CXS70-14-C" Panduit_CXS70-14-C 5590,1275 r180 top
TP1 "RCU-0C" TE_RCU 3275,1160 r0 top
TP2 "RCU-0C" TE_RCU 3275,2365 r0 top
TP3 "RCU-0C" TE_RCU 3034.47,1579.93 r180 top
TP4 "RCU-0C" TE_RCU 3032.2,1969.98 r180 top
TP5 "5006" Keystone5006 3991.79,1593.49 r0 top
U1 "LM5125AQRHBRQ1" RHB0032U-MFG 2559,1775 r90 top
ZZ2 "These assemblies are ESD sensitive, ESD precautions shall be observed." AssemblyNote 185,4250 r0 top
ZZ3 "These assemblies must be clean and free from flux and all contaminants. Use of no clean flux is not acceptable." AssemblyNote 185,4350 r0 top
ZZ4 "These assemblies must comply with workmanship standards IPC-A-610 Class 2, unless otherwise specified." AssemblyNote 185,4450 r0 top
ZZ5 "Install Shunt Jumper SH-JP1 onto JP1 pins 1-2" AssemblyNote 185,4550 r0 top
ZZ6 "Install Shunt Jumper SH-JP2 onto JP2 pins 1-2" AssemblyNote 185,4650 r0 top
ZZ7 "Install Shunt Jumper SH-JP3 onto JP3 pins 2-3" AssemblyNote 185,4750 r0 top
ZZ8 "Install Shunt Jumper SH-JP4 onto JP4" AssemblyNote 185,4850 r0 top
ZZ9 "Install Shunt Jumper SH-JP5 onto JP5" AssemblyNote 189.02,4940.94 r0 top
ZZ10 "Install Shunt Jumper SH-JP6 onto JP6" AssemblyNote 189.02,5029.53 r0 top

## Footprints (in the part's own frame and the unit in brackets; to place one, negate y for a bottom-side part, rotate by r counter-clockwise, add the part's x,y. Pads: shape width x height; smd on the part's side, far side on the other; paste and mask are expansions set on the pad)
0402S [mil] "Based on C0402S footprint from PADS legacy"
  rect 15x24 smd: 1(-20,0) 2(20,0)
  body extent -22,-12 22,12, height 24
0603S [mil]
  rect 20x35 smd: 1(-30,0) 2(30,0)
  body extent -34,-19 34,19, height 39
0805L [mm] "0805 from SM-752 data"
  rect 1.1x1.4 smd: 1(-0.75,0) 2(0.75,0)
  body extent -1.1,-0.72 1.1,0.72, height 1.45
1206L [mm] "1206 from SM-752 data"
  rect 1.1x1.75 smd: 1(-1.35,0) 2(1.35,0)
  silkscreen extent -0.4,-0.77 0.4,0.77, body extent -1.7,-0.9 1.7,0.9, height 1.35
2512_WIDE [mm] "Ohmite recommended land pattern"
  rect 1x6.6 smd: 1(-1.6,0) 2(1.6,0)
  silkscreen extent -0.82,-3.32 0.82,3.35, body extent -1.65,-3.25 1.65,3.25, height 0.7
AssemblyNote [mil] "Assembly Note"
CONN_2510-6002 [mm] "3M 2500 series TS-0770-L December 15, 2011"
  rect 1.65x1.65 hole 1.016 mask+0: 1(-5.08,-1.27)
  round 1.65 hole 1.016 mask+0: 2(-5.08,1.27) 3(-2.54,-1.27) 4(-2.54,1.27) 5(0,-1.27) 6(0,1.27) 7(2.54,-1.27) 8(2.54,1.27) 9(5.08,-1.27) 10(5.08,1.27)
  silkscreen extent -10.01,-4.17 10.01,4.47, body extent -10.01,-4.11 10.01,4.52, height 9.92
Fiducial10-20 [mm]
  round 1 smd mask+0.5: 1(0,0)
  Top Layer keep-out circle w1.178: c0,0 r0.5
FP-EEHZU1H221P_RADIAL_SMT-MFG [mm]
  rrect5% 4.1x2 smd paste+0 mask+0: 1(-4.35,0) 2(4.35,0)
  silkscreen extent -7.07,-5.25 5.25,5.25, body extent -6.65,-5.5 6.65,5.5, height 0.25
FP-EEHZU1J151P_RADIAL_SMT-MFG [mm]
  rrect5% 4.1x2 smd paste+0 mask+0: 1(-4.35,0) 2(4.35,0)
  silkscreen extent -7.07,-5.25 5.25,5.25, body extent -6.65,-5.5 6.65,5.5, height 0.25
FP-GRM32EC72A106KE05L_1210-MFG [mm]
  rrect9% 1.1x2.05 smd paste+0 mask+0: 1(-1.65,0) 2(1.65,0)
  silkscreen extent -0.72,-1.35 0.72,1.35, body extent -2.3,-1.45 2.3,1.45, height 0.25
FP-WSL080500000ZEA9_0805-MFG [mm]
  rrect10% 1.02x1.27 smd paste+0 mask+0: 1(-0.76,0) 2(0.76,0)
  silkscreen extent -1.14,-1.05 1.14,1.05, body extent -1.37,-0.86 1.37,0.86, height 0.25
IEC_HotSurface_Small [mil]
  silkscreen extent -107,-93 107,92
IHLP-6767GZ [mm] "SMD, 2-Leads, Body 17.15x17.15mm"
  rrect3% 3.825x12.32 smd: 1(-8.123,0) 2(8.123,0)
  silkscreen extent -8.64,-8.57 8.64,8.57, body extent -8.59,-8.59 8.59,8.59, height 6.9
Johnson_108-0740-001 [mm] "Banana Jack Uninsulated Standard Type"
  round 12 hole 6.858: 1(0,0)
  body extent -4.77,-5.43 4.75,5.57, height 2.39
Keystone5006 [mil] "Keystone Compact loops"
  round 87 hole 63: 1(0,0)
  silkscreen extent -70,-70 70,70, body extent -63,-63 62,63, height 225
Keystone_1902C [mil] "Hex Standoff, 4-40 threaded, nylon"
  round 1 on Mech4: 0(0,0)
  body extent -145,-126 146,126, height 501
Net-Tie_10milWide_30milLong [mil] "10mil net tie, no solder mask opening, no solder paste"
  rect 30x10 smd paste-5 mask-5: 1(-15,0) 2(15,0)
"NY PMS 440 0025 PH" [mm] "4-40 nylon screw and mounting hole"
  round 8 hole 3.2: 1(0,0)
  body extent -3.3,-3.3 3.3,3.3, height 2.69
Panduit_CXS70-14-C [mil] "Panduit"
  rect 770x500 hole 270 copper offset -74.8,0 paste-99999: 1(0,0)
  body extent -960,-250 310,250, height 684
RHB0032U-MFG [mm] "Recommended Land Pattern"
  rrect40% 0.6x0.25 smd paste+0 mask+0: 1(-2.4,1.75) 2(-2.4,1.25) 3(-2.4,0.75) 4(-2.4,0.25) 5(-2.4,-0.25) 6(-2.4,-0.75) 7(-2.4,-1.25) 8(-2.4,-1.75) 17(2.4,-1.75) 18(2.4,-1.25) 19(2.4,-0.75) 20(2.4,-0.25) 21(2.4,0.25) 22(2.4,0.75) 23(2.4,1.25) 24(2.4,1.75)
  rrect40% 0.25x0.6 smd paste+0 mask+0: 9(-1.75,-2.4) 10(-1.25,-2.4) 11(-0.75,-2.4) 12(-0.25,-2.4) 13(0.25,-2.4) 14(0.75,-2.4) 15(1.25,-2.4) 16(1.75,-2.4) 25(1.75,2.4) 26(1.25,2.4) 27(0.75,2.4) 28(0.25,2.4) 29(-0.25,2.4) 30(-0.75,2.4) 31(-1.25,2.4) 32(-1.75,2.4)
  rrect3% 3.7x3.7 smd paste-1000 mask+0: 33(0,0)
  silkscreen extent -3.37,-2.55 2.55,2.55, body extent -2.5,-2.5 2.5,2.5, height 1
SO-8FL [mm] "ON SEMICONDUCTOR, DFN5 5x6, 1.27P, CASE 488AA"
  rect 1x0.75 smd: 1(-2.795,1.905) 2(-2.795,0.635) 3(-2.795,-0.635) 4(-2.795,-1.905)
  rect 4.055x4.56 smd: 5(0.698,0)
  Top Layer region: 0,-2.775 0,2.775 -0.905,2.775 -0.905,-2.775
  Top Layer region: 3.2,1.53 3.2,2.28 2.655,2.28 2.655,1.53
  Top Layer region: 3.2,-2.28 3.2,-1.53 2.65,-1.53 2.65,-2.28
  silkscreen extent -3.1,-2.6 3.1,2.9, body extent -3.17,-2.67 3.17,2.67, height 1.11
SPC02SYAN [mil] "SULLINS"
  round 1 on Mech3: 0(0,0)
  body extent -98,-47 99,47, height 366
SW_218-8LP [mm] "SMD, 16-Leads, Body 11.33x5.8mm, Pitch 1.27mm"
  rect 1.27x0.76 smd: 1(-3.81,4.445) 2(-3.81,3.175) 3(-3.81,1.905) 4(-3.81,0.635) 5(-3.81,-0.635) 6(-3.81,-1.905) 7(-3.81,-3.175) 8(-3.81,-4.445) 9(3.81,-4.445) 10(3.81,-3.175) 11(3.81,-1.905) 12(3.81,-0.635) 13(3.81,0.635) 14(3.81,1.905) 15(3.81,3.175) 16(3.81,4.445)
  silkscreen extent -2.9,-5.67 2.9,5.9, body extent -4.22,-5.66 4.22,5.66, height 2.62
TE_RCU [mm] "SMD, 1-Leads, Body 1.6x0.8mm"
  rrect8% 2.4x1.2 smd: 1(0,0)
  body extent -0.8,-0.45 0.8,0.45, height 1.15
TO-277A [mm] "Vishay"
  rect 1.4x1.27 smd: 1(-1.04,1.83) 2(1.04,1.83)
  rect 4.72x4.8 smd: 3(0,-1.883)
  silkscreen extent -2.7,1.45 -2.4,1.75, body extent -2.35,-4.2 2.4,2.45, height 1.2
TSW-112-07-G-D [mm] "Samtec 100mil, 2x12, 230 mil above insulator"
  rrect6% 1.65x1.65 hole 1.016: 1(-13.97,-1.27)
  round 1.65 hole 1.016: 2(-13.97,1.27) 3(-11.43,-1.27) 4(-11.43,1.27) 5(-8.89,-1.27) 6(-8.89,1.27) 7(-6.35,-1.27) 8(-6.35,1.27) 9(-3.81,-1.27) 10(-3.81,1.27) 11(-1.27,-1.27) 12(-1.27,1.27) 13(1.27,-1.27) 14(1.27,1.27) 15(3.81,-1.27) 16(3.81,1.27) 17(6.35,-1.27) 18(6.35,1.27) 19(8.89,-1.27) 20(8.89,1.27) 21(11.43,-1.27) 22(11.43,1.27) 23(13.97,-1.27) 24(13.97,1.27)
  silkscreen extent -16.27,-2.54 15.24,2.54, body extent -15.24,-2.54 15.24,2.54, height 8.38
WURTH_61300111121 [mm] "Header, 2.54 mm, 1x1, TH"
  rect 1.65x1.65 hole 1.15: 1(0,0)
  silkscreen extent -1.27,-1.27 1.27,1.27, body extent -1.27,-1.27 1.27,1.27, height 8.54
WURTH_61300211121 [mm] "Header, 2.54mm, 2x1, TH"
  rrect50% 1.65x1.65 hole 1.15: 1(-1.27,0)
  round 1.65 hole 1.15: 2(1.27,0)
  body extent -2.54,-1.27 2.54,1.27, height 8.54
WURTH_61300311121 [mm] "Header, 2.54mm, 3x1, TH"
  rrect50% 1.65x1.65 hole 1.15: 1(-2.54,0)
  round 1.65 hole 1.15: 2(0,0) 3(2.54,0)
  body extent -3.81,-1.27 3.81,1.27, height 8.54

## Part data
C1 C3 C13 C14 C15 C29 C30 C41 C42 C43 C44 C45 C46 C47 C48 C49 C50 C51 C52 C53 C54 C55 C56 C57 C58 C59 C60 C69: library part CMP-0007469-4, "CAP, CERM, 0.1 uF, 100 V, +/- 10%, X7R, 0603", Cap_Case=0603, Manufacturer=MuRata, Supplier Part Number 1=490-3285-1-ND, TempCo=X7R, Tolerance_%=10%, Value1=Unknown, Value2=100V, ValueDisplayed=0.1uF
C2: library part CMP-0086249-1, "CAP, CERM, 1 µF, 50 V,+/- 10%, X7R, AEC-Q200 Grade 1, 0805", Cap_Case=0805, Manufacturer=MuRata, TempCo=X7R, Tolerance_%=10%, Value2=50V, ValueDisplayed=1µF
C4: library part CMP-0079153-1, "CAP, CERM, 10 µF, 10 V,+/- 10%, X7R, AEC-Q200 Grade 1, 0805", Cap_Case=0805, Manufacturer=MuRata, Supplier Part Number 1=490-12646-1-ND, TempCo=X7R, Tolerance_%=10%, Value2=10V, ValueDisplayed=10µF
C5: library part CMP-0007147-5, "CAP, CERM, 0.015 uF, 100 V, +/- 10%, X7R, AEC-Q200 Grade 1, 0603", Cap_Case=0603, Manufacturer=MuRata, Supplier Part Number 1=490-8029-1-ND, TempCo=X7R, Tolerance_%=10%, Value1=Unknown, Value2=100V, ValueDisplayed=0.015uF
C6: library part CMP-0007064-4, "CAP, CERM, 500 pF, 50 V, +/- 5%, C0G/NP0, 0603", Cap_Case=0603, Manufacturer="Yageo America", Supplier Part Number 1=CC0603JRNPO9BN501-ND, TempCo=C0G/NP0, Tolerance_%=5%, Value1=Unknown, Value2=50V, ValueDisplayed=500pF
C7: library part CMP-0006988-4, "CAP, CERM, 10 pF, 50 V, +/- 5%, C0G/NP0, 0603", Cap_Case=0603, Manufacturer=TDK, Supplier Part Number 1=445-1269-1-ND, TempCo=C0G/NP0, Tolerance_%=5%, Value1="0.3492 ohm", Value2=50V, ValueDisplayed=10pF
C8: library part CMP-0006925-5, "CAP, CERM, 0.33 uF, 10 V, +/- 10%, X5R, 0603", Cap_Case=0603, Manufacturer=Kemet, Supplier Part Number 1=399-3112-1-ND, TempCo=X5R, Tolerance_%=10%, Value1=Unknown, Value2=10V, ValueDisplayed=0.33uF
C9 C10: library part CMP-0006960-4, "CAP, CERM, 680 pF, 50 V, +/- 10%, X7R, 0603", Cap_Case=0603, Manufacturer=Kemet, Supplier Part Number 1=399-1077-1-ND, TempCo=X7R, Tolerance_%=10%, Value1=Unknown, Value2=50V, ValueDisplayed=680pF
C11 C12: library part CMP-0085815-1, "CAP, CERM, 68 pF, 50 V,+/- 1%, C0G/NP0, 0402", Cap_Case=0402, Manufacturer=AVX, TempCo=C0G/NP0, Tolerance_%=1%, Value2=50V, ValueDisplayed=68pF
C16: library part CMP-0007868-2, "CAP, CERM, 3.3 uF, 25 V, +/- 10%, X7R, 0805", Cap_Case=0805, Manufacturer=TDK, Supplier Part Number 1=445-5970-1-ND, TempCo=X7R, Tolerance_%=10%, Value1=Unknown, Value2=25V, ValueDisplayed=3.3uF
C17: library part CMP-0006989-4, "CAP, CERM, 100 pF, 50 V, +/- 5%, C0G/NP0, 0603", Cap_Case=0603, Manufacturer=TDK, Supplier Part Number 1=445-173611-1-ND, TempCo=C0G/NP0, Tolerance_%=5%, Value1=Unknown, Value2=50V, ValueDisplayed=100pF
C18 C19: library part CMP-0007049-4, "CAP, CERM, 0.047 uF, 50 V, +/- 10%, X7R, 0603", Cap_Case=0603, Manufacturer=TDK, Supplier Part Number 1=445-1313-1-ND, TempCo=X7R, Tolerance_%=10%, Value1="0.049007 ohm", Value2=50V, ValueDisplayed=0.047uF
C20: library part CMP-0007969-2, "CAP, CERM, 0.1 uF, 100 V, +/- 10%, X7R, AEC-Q200 Grade 1, 0805", Cap_Case=0805, Manufacturer=TDK, Supplier Part Number 1=445-5827-1-ND, TempCo=X7R, Tolerance_%=10%, Value1="0.020726 ohm", Value2=100V, ValueDisplayed=0.1uF
C21 C22 C23 C24 C31 C32 C33 C34 C35 C36 C37 C38 C39 C40: library part CMP-0087970-1, "10µF ±10% 100V Ceramic Capacitor X7S 1210 (3225 Metric)", Manufacturer=Murata, TempCo=22%, Tolerance_%=10%, ValueDisplayed=10uF
C25 C26 C27 C28: library part CMP-0120360-1, "Aluminum Hybrid Polymer Capacitors 220uF 20% 50V Life 4000Hours AEC-Q200 RADIAL SMT", Leakage Current=110uA, Manufacturer=Panasonic, Operating Temperature Range="-55°C to +135°C", Tolerance_%=20%, ValueDisplayed=220uF
C61 C62 C63 C64 C65 C66 C67 C68: library part CMP-0120392-1, "Aluminum Hybrid Polymer Capacitors 150uF 20% 63V Life 4000Hours AEC-Q200 RADIAL SMT", Leakage Current=94.5uA, Manufacturer=Panasonic, Operating Temperature Range="-55°C to +135°C", Tolerance_%=20%, ValueDisplayed=150uF
D1 D2 D3 D4: library part CMP-0028832-2, "Diode, Schottky, 100 V, 12 A, AEC-Q101, TO-277A", Manufacturer=Vishay-Semiconductor, Value1=12A, Value2=0.7V
FID1 FID2 FID3: library part CMP-0077181-1, "Fiducial mark.  There is nothing to buy or mount.", Manufacturer=N/A
H1 H2 H3 H4: library part CMP-0003617-1, "Machine Screw, Round, #4-40 x 1/4, Nylon, Philips panhead", Manufacturer="B&F Fastener Supply", Supplier Part Number 1=H542-ND
H5 H6 H7 H8: library part CMP-0003610-1, "Standoff, Hex, 0.5\"L #4-40 Nylon", Manufacturer=Keystone, Supplier Part Number 1=36-1902C-ND
J1 J2 J3 J4: library part CMP-0055387-2, "Standard Banana Jack, Uninsulated, 15A", Manufacturer="Cinch Connectivity", Supplier Part Number 1=J147-ND
J5 J6 J7 J8 J11 J12 JP4 JP5 JP6: library part CMP-0054794-2, "Header, 2.54 mm, 2x1, Gold, TH", Color=Black, Manufacturer="Wurth Elektronik", Supplier Part Number 1=732-5315-ND
J9 J10: library part CMP-0075423-1, "Header, 100mil, 12x2, Gold, TH", Color=Black, Current_A=6.3A, Manufacturer=Samtec, Supplier Part Number 1=SAM1028-12-ND, Voltage_V=550V
J13: library part CMP-0055448-2, "Header (shrouded), 100mil, 5x2, High-Temperature, Gold, TH", Manufacturer=3M, PartNumber=N2510-6002-RB, Supplier Part Number 1=MHC10K-ND
J14: library part CMP-0054792-1, "Header, 2.54 mm, 1x1, Gold, TH", Manufacturer="Wurth Elektronik", Supplier Part Number 1=732-5314-ND
JP1 JP2 JP3: library part CMP-0054796-4, "Header, 2.54 mm, 3x1, Gold, TH", Manufacturer="Wurth Elektronik", Supplier Part Number 1=732-5316-ND
L1 L2: library part CMP-0750174-1, "Inductor, Shielded, 3.3 µH, 32.2 A, 0.00327 ohm, AEC-Q200 Grade 0, SMD", Manufacturer=Vishay-Dale, Value1="0.00327 ohm", Value2=32.2A, ValueDisplayed=3.3µH
Logo5 Logo6: library part CMP-0074837-2, "IEC 61010-1 Hot Surface Warning", Manufacturer="Texas Instruments"
NT1: library part CMP-0078142-6, "Single point connection between nets.", Manufacturer=N/A
Q1 Q2 Q3 Q4 Q5 Q6 Q7 Q8: library part CMP-0000853-1, "MOSFET, N-CH, 60 V, 71 A, SO-8FL", Alternate Manufacturer=None, Manufacturer="ON Semiconductor", PartNumber=NTMFS5C670NLT1G, Supplier Part Number 1=NTMFS5C670NLT1GOSCT-ND, Value1=0.008, Value2="20 nC"
R1 R2 R3 R4: library part CMP-0084409-1, "RES, 0.0015, 5%, 2 W, 2512 WIDE", Manufacturer=Rohm, Power_W=2W, TempCo="100 ppm/C", Tolerance_%=5%, Value_Code=1L500, ValueDisplayed=0.0015
R5: library part CMP-0022204-4, "RES, 20.0 k, 1%, 0.1 W, AEC-Q200 Grade 0, 0603", Manufacturer=Vishay-Dale, Power_W=100mW, Supplier Part Number 1=541-20.0KHCT-ND, TempCo="100 ppm/C", Tolerance_%=1%, Value2=0.1W, Value_Code=20k0, ValueDisplayed=20.0k
R6: library part CMP-0024471-3, "RES, 78.7 k, 0.1%, 0.1 W, 0603", Manufacturer="Yageo America", Power_W=100mW, TempCo="25 ppm/C", Tolerance_%=0.1%, Value2=0.1W, Value_Code=78k7, ValueDisplayed=78.7k
R7: library part CMP-0024266-3, "RES, 47.5 k, 0.1%, 0.1 W, 0603", Manufacturer="Yageo America", Power_W=100mW, TempCo="25 ppm/C", Tolerance_%=0.1%, Value2=0.1W, Value_Code=47k5, ValueDisplayed=47.5k
R8: library part CMP-0022558-4, "RES, 6.04 k, 1%, 0.1 W, AEC-Q200 Grade 0, 0603", Manufacturer=Vishay-Dale, Power_W=100mW, Supplier Part Number 1=541-6.04KHCT-ND, TempCo="100 ppm/C", Tolerance_%=1%, Value2=0.1W, Value_Code=6k04, ValueDisplayed=6.04k
R9 R94: library part CMP-0021424-3, "RES, 75.0 k, 1%, 0.125 W, AEC-Q200 Grade 0, 0805", Manufacturer=Vishay-Dale, Power_W=125mW, Supplier Part Number 1=541-75.0KCCT-ND, TempCo="100 ppm/C", Tolerance_%=1%, Value2=0.125W, Value_Code=75k0, ValueDisplayed=75.0k
R10: library part CMP-0020536-3, "RES, 39 k, 5%, 0.125 W, AEC-Q200 Grade 0, 0805", Manufacturer=Vishay-Dale, Power_W=125mW, Supplier Part Number 1=541-39KACT-ND, TempCo="200 ppm/C", Tolerance_%=5%, Value2=0.125W, Value_Code=39k0, ValueDisplayed=39k
R11 R12 R13 R14: library part CMP-0122265-1, "0 Ohms Jumper Chip Resistor 0805 (2012 Metric) Metal Element", Digikey Part Number=541-3928-1-ND, Manufacturer=Vishay, Mouser Part Number=71-WSL080500000ZEA9, Operating Temperature Range="-65°C to +170°C", Power_W=125mW, TempCo=3900ppm/°C
R15 R16 R17 R18 R39 R40 R41 R57 R73: library part CMP-0023343-3, "RES, 0, 1%, 0.1 W, AEC-Q200 Grade 0, 0603", Manufacturer="Stackpole Electronics Inc", Power_W=100mW, Supplier Part Number 1=RMCF0603ZT0R00CT-ND, TempCo=ppm/C, Tolerance_%=1%, Value2=0.1W, Value_Code=0
R19: library part CMP-0021990-4, "RES, 100 k, 1%, 0.1 W, AEC-Q200 Grade 0, 0603", Manufacturer=Vishay-Dale, Power_W=100mW, Supplier Part Number 1=541-100KHCT-ND, TempCo="100 ppm/C", Tolerance_%=1%, Value2=0.1W, Value_Code=100k
R20 R22 R24 R26 R28: library part CMP-0022003-4, "RES, 10.0, 1%, 0.1 W, AEC-Q200 Grade 0, 0603", Manufacturer=Vishay-Dale, Power_W=100mW, Supplier Part Number 1=541-10.0HCT-ND, TempCo="100 ppm/C", Tolerance_%=1%, Value2=0.1W, Value_Code=10R0, ValueDisplayed=10.0
R21 R23 R25 R27: library part CMP-0022711-2, "RES, 2.20, 1%, 0.1 W, 0603", Manufacturer=Panasonic, Power_W=100mW, Supplier Part Number 1=P2.2AJCT-ND, TempCo="200 ppm/C", Tolerance_%=1%, Value2=0.1W, Value_Code=2R20, ValueDisplayed=2.20
R29 R30: library part CMP-0016971-3, "RES, 3.24, 1%, 0.25 W, AEC-Q200 Grade 0, 1206", Manufacturer=Vishay-Dale, Power_W=250mW, Supplier Part Number 1=541-3.24FFCT-ND, TempCo="100 ppm/C", Tolerance_%=1%, Value2=0.25W, Value_Code=3R24, ValueDisplayed=3.24
R31 R32 R33 R34 R35 R36 R37 R38: library part CMP-0025950-3, "RES, 100 k, 1%, 0.063 W, AEC-Q200 Grade 0, 0402", Manufacturer=Vishay-Dale, Power_W=63mW, Supplier Part Number 1=541-100KLCT-ND, TempCo="100 ppm/C", Tolerance_%=1%, Value2=0.063W, Value_Code=100k
R42 R58 R74: library part CMP-0022481-5, "RES, 511, 1%, 0.1 W, AEC-Q200 Grade 0, 0603", Manufacturer=Vishay-Dale, Power_W=100mW, Supplier Part Number 1=541-511HCT-ND, TempCo="100 ppm/C", Tolerance_%=1%, Value2=0.1W, Value_Code=511R, ValueDisplayed=511
R43 R59 R75: library part CMP-0022120-4, "RES, 1.30 k, 1%, 0.1 W, AEC-Q200 Grade 0, 0603", Manufacturer=Vishay-Dale, Power_W=100mW, Supplier Part Number 1=541-1.30KHCT-ND, TempCo="100 ppm/C", Tolerance_%=1%, Value2=0.1W, Value_Code=1k30, ValueDisplayed=1.30k
R44 R60 R76: library part CMP-0022135-4, "RES, 1.87 k, 1%, 0.1 W, AEC-Q200 Grade 0, 0603", Manufacturer=Vishay-Dale, Power_W=100mW, Supplier Part Number 1=541-1.87KHCT-ND, TempCo="100 ppm/C", Tolerance_%=1%, Value2=0.1W, Value_Code=1k87, ValueDisplayed=1.87k
R45 R61 R77: library part CMP-0022281-4, "RES, 2.74 k, 1%, 0.1 W, AEC-Q200 Grade 0, 0603", Manufacturer=Vishay-Dale, Power_W=100mW, Supplier Part Number 1=541-2.74KHCT-ND, TempCo="100 ppm/C", Tolerance_%=1%, Value2=0.1W, Value_Code=2k74, ValueDisplayed=2.74k
R46 R62 R78: library part CMP-0022381-4, "RES, 3.83 k, 1%, 0.1 W, AEC-Q200 Grade 0, 0603", Manufacturer=Vishay-Dale, Power_W=100mW, Supplier Part Number 1=541-3.83KHCT-ND, TempCo="100 ppm/C", Tolerance_%=1%, Value2=0.1W, Value_Code=3k83, ValueDisplayed=3.83k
